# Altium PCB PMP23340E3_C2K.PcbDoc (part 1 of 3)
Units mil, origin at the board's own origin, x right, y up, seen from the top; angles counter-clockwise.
Board outline 2299.21 x 1157.48 mil, 14 copper layers (Top Layer, Layer 1, Layer 2, Layer 3, Layer 4, Layer 5, Layer 6, Layer 7, Layer 8, Layer 9, Layer 10, Layer 11, Layer 12, Bottom Layer), stack 130 mil thick; 241 components, 70 nets, 1009 pads, 327 vias.
Unrouted connection lines stored in the file: 7.
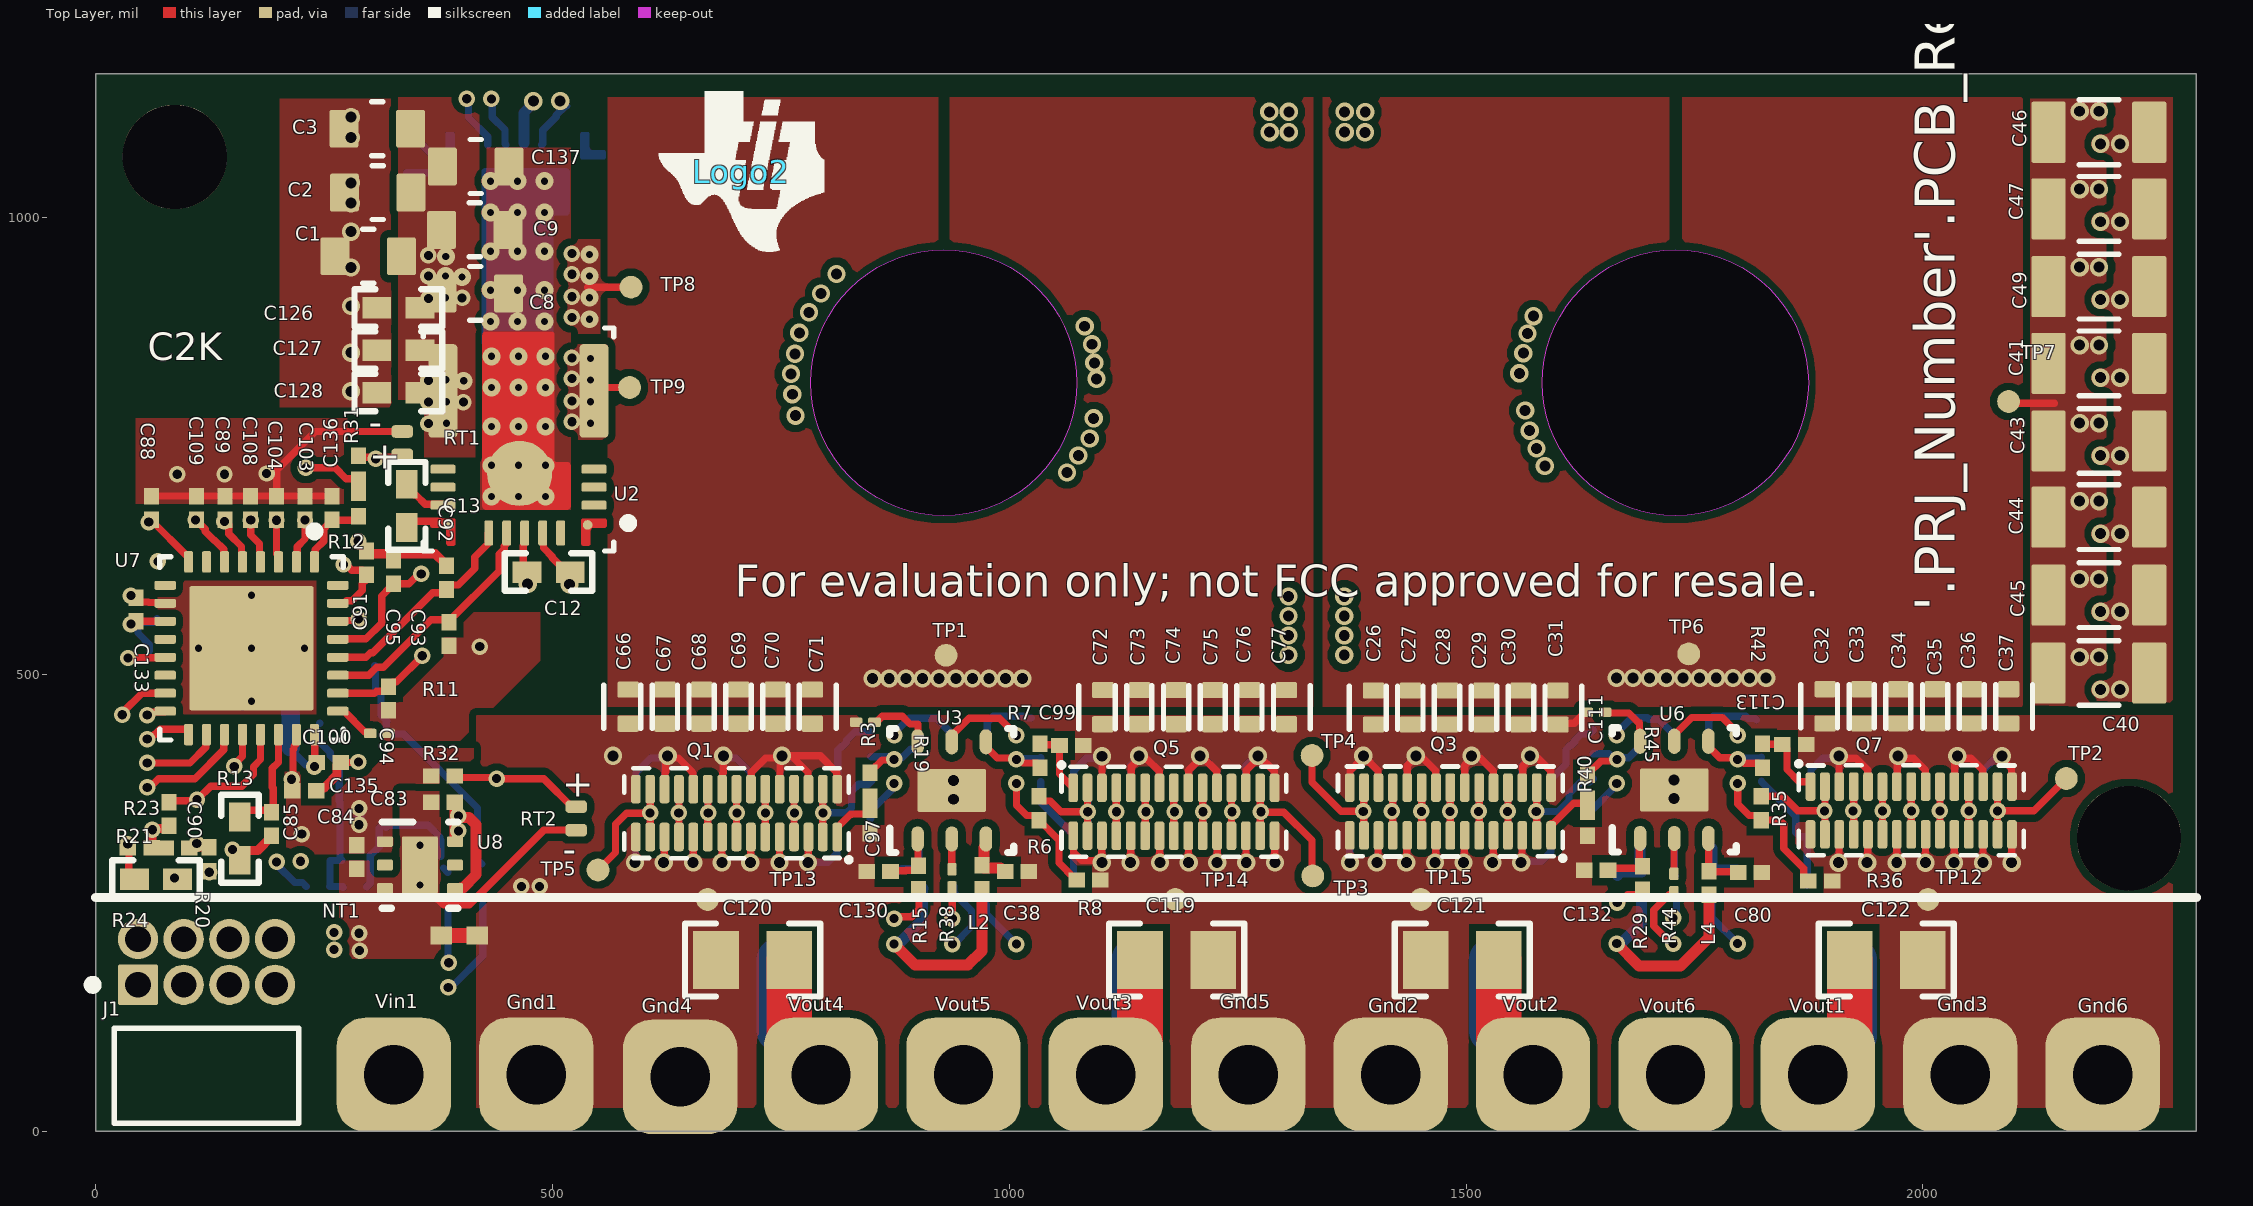
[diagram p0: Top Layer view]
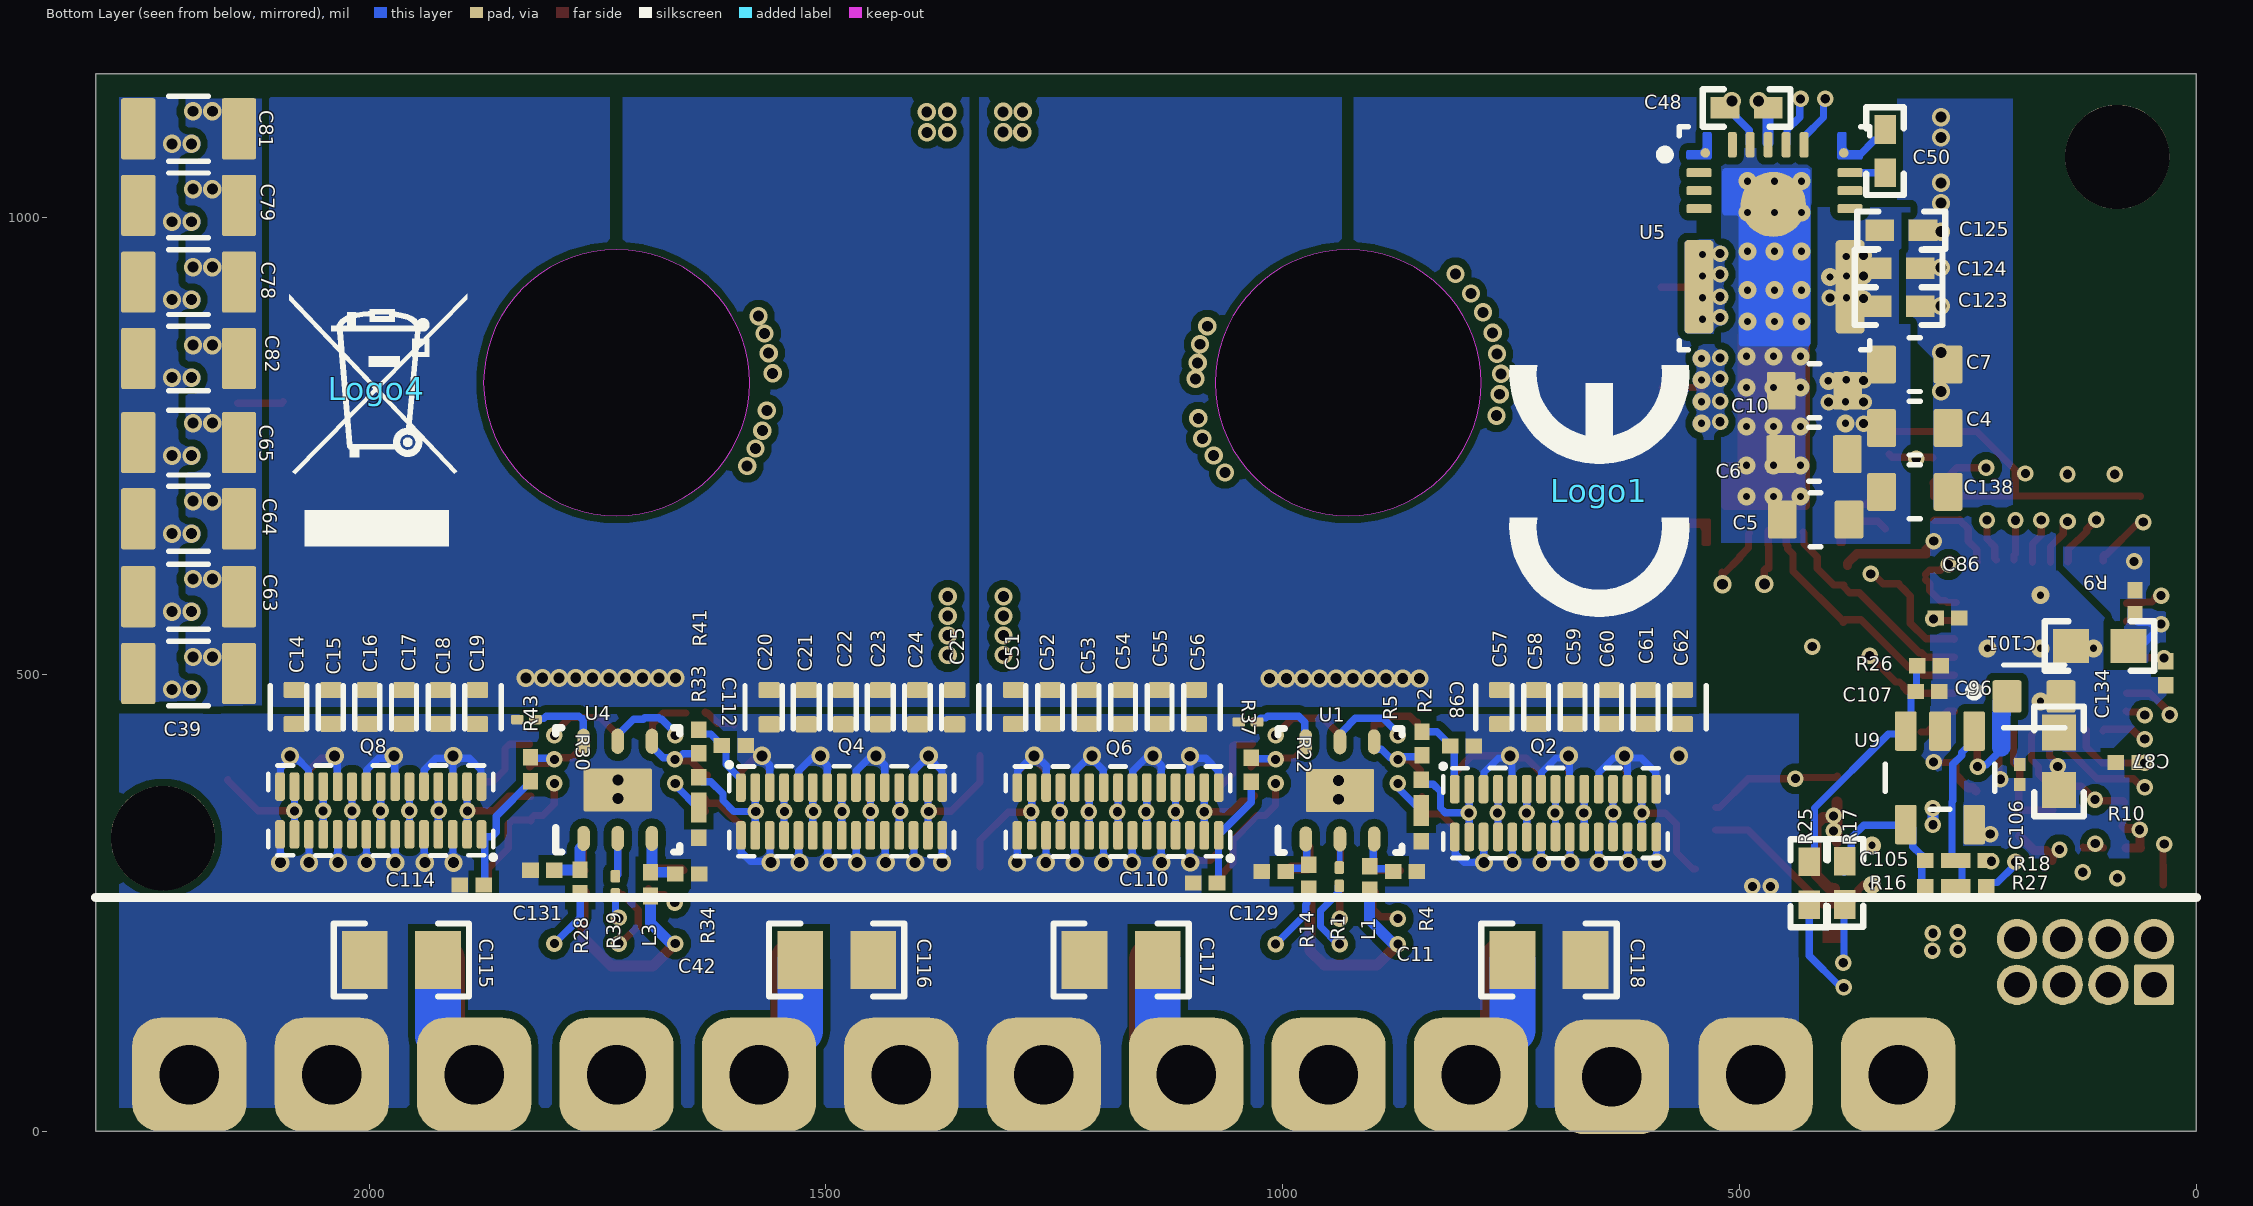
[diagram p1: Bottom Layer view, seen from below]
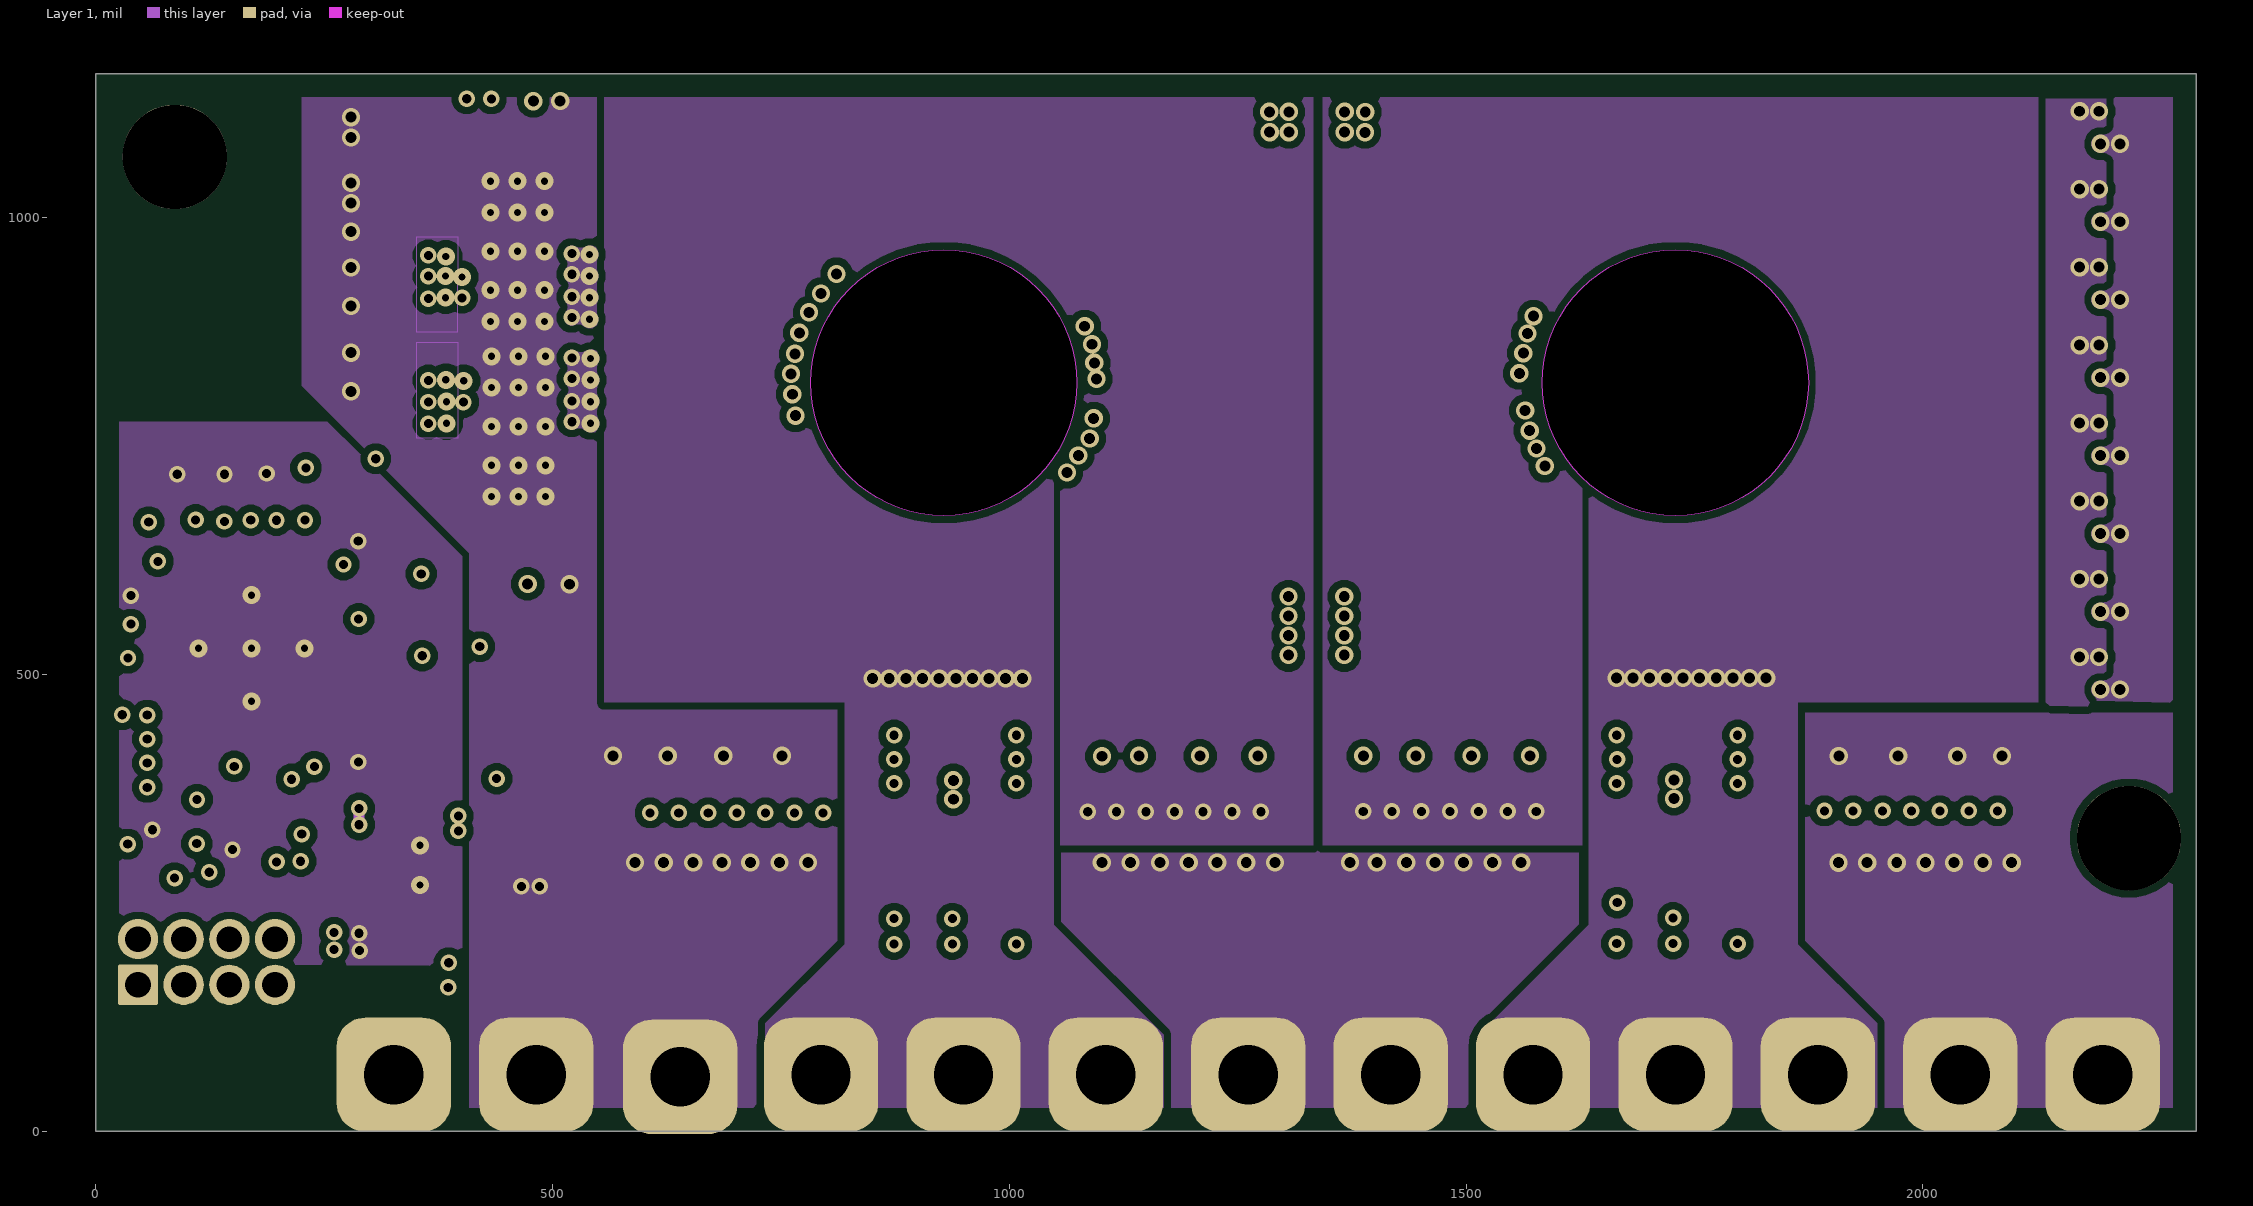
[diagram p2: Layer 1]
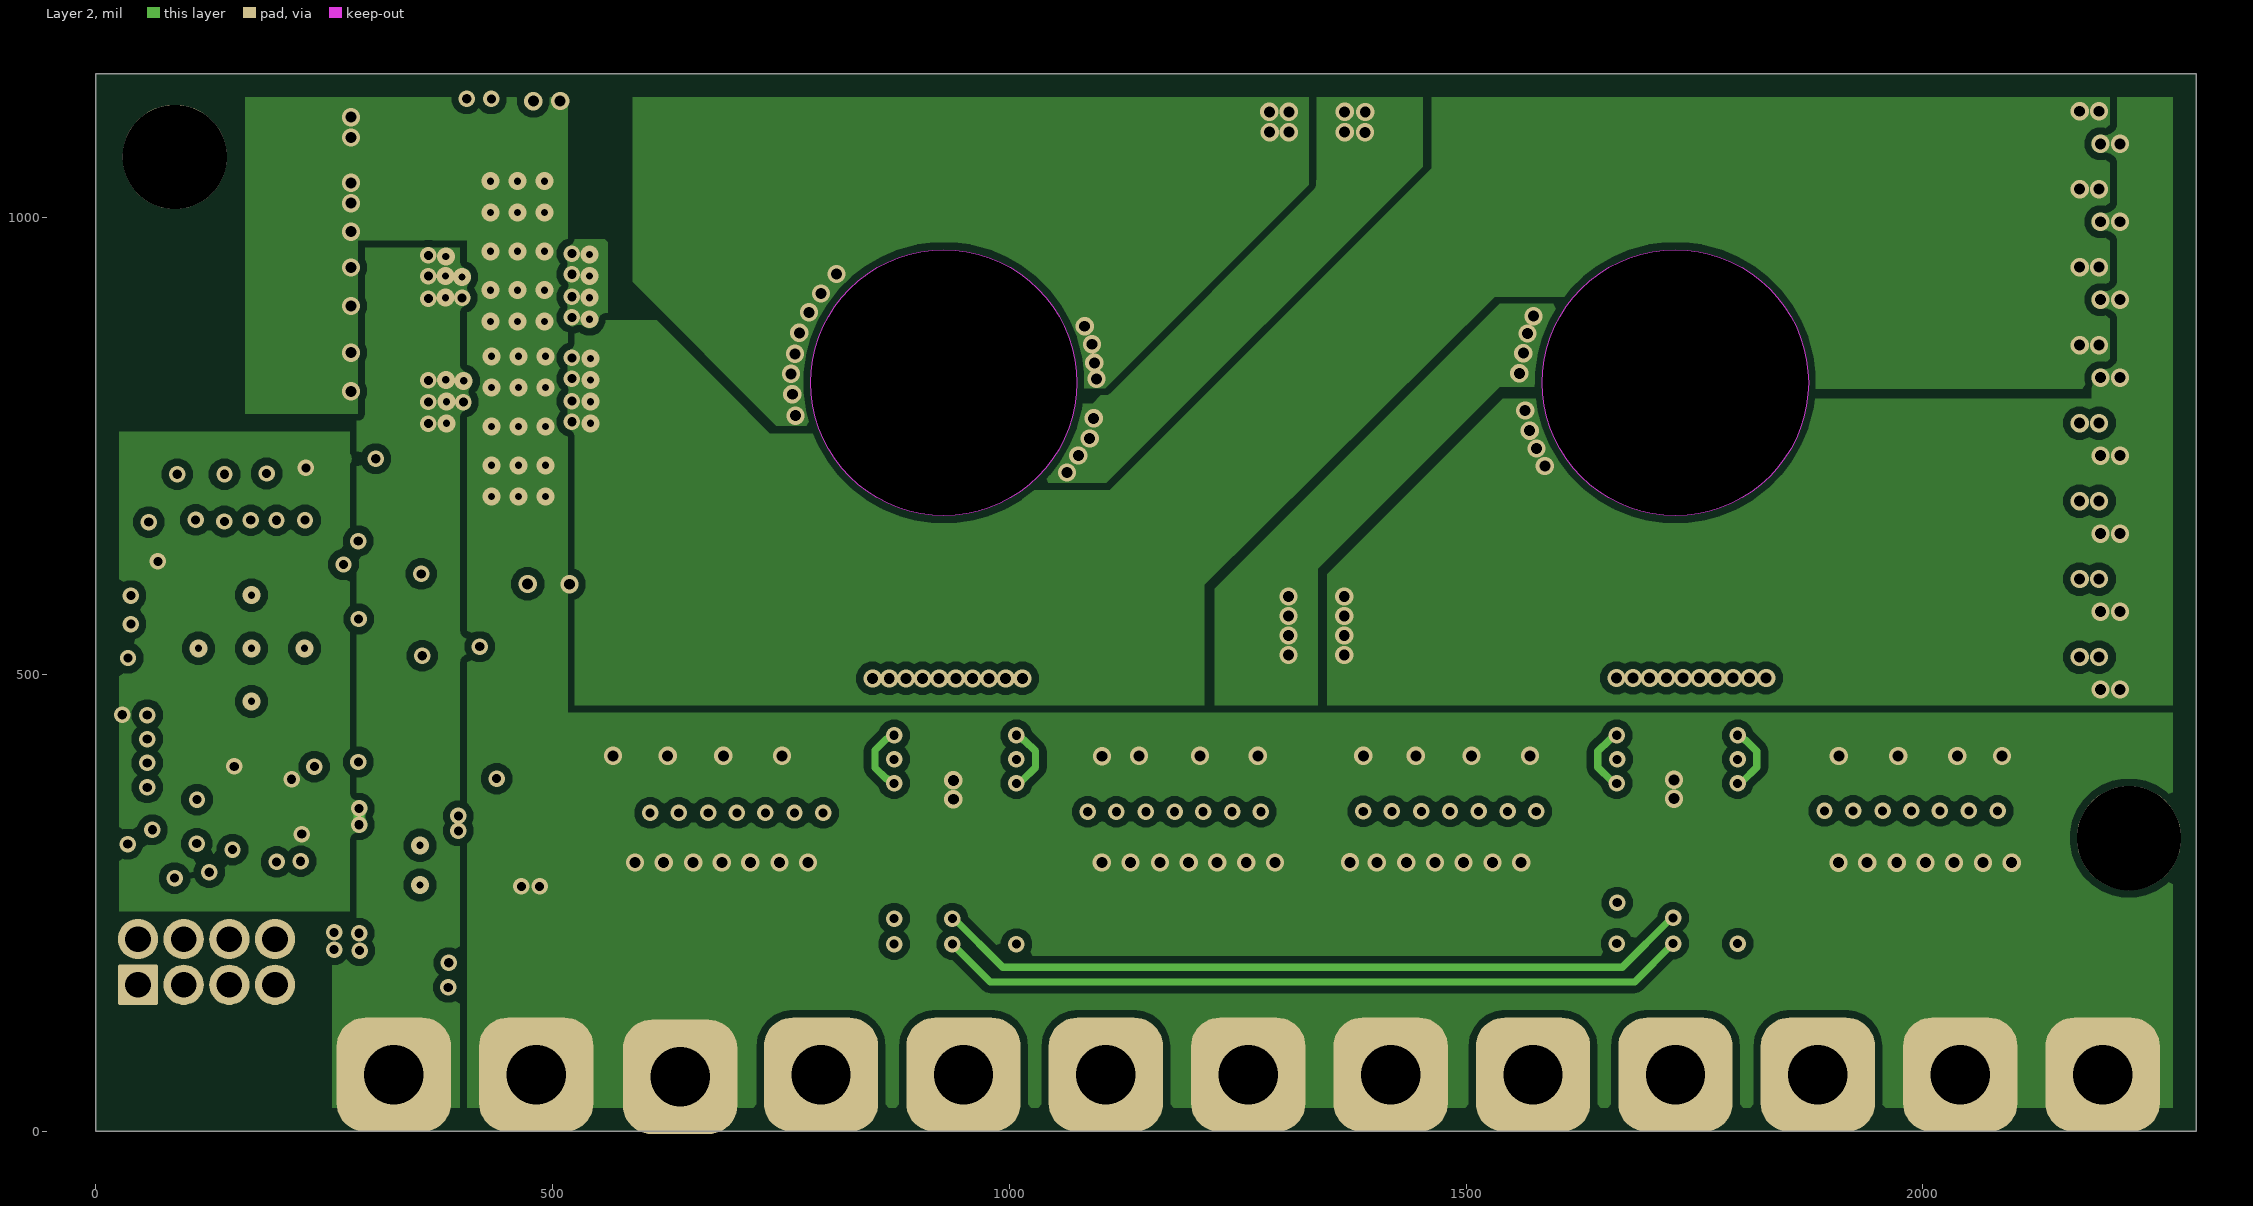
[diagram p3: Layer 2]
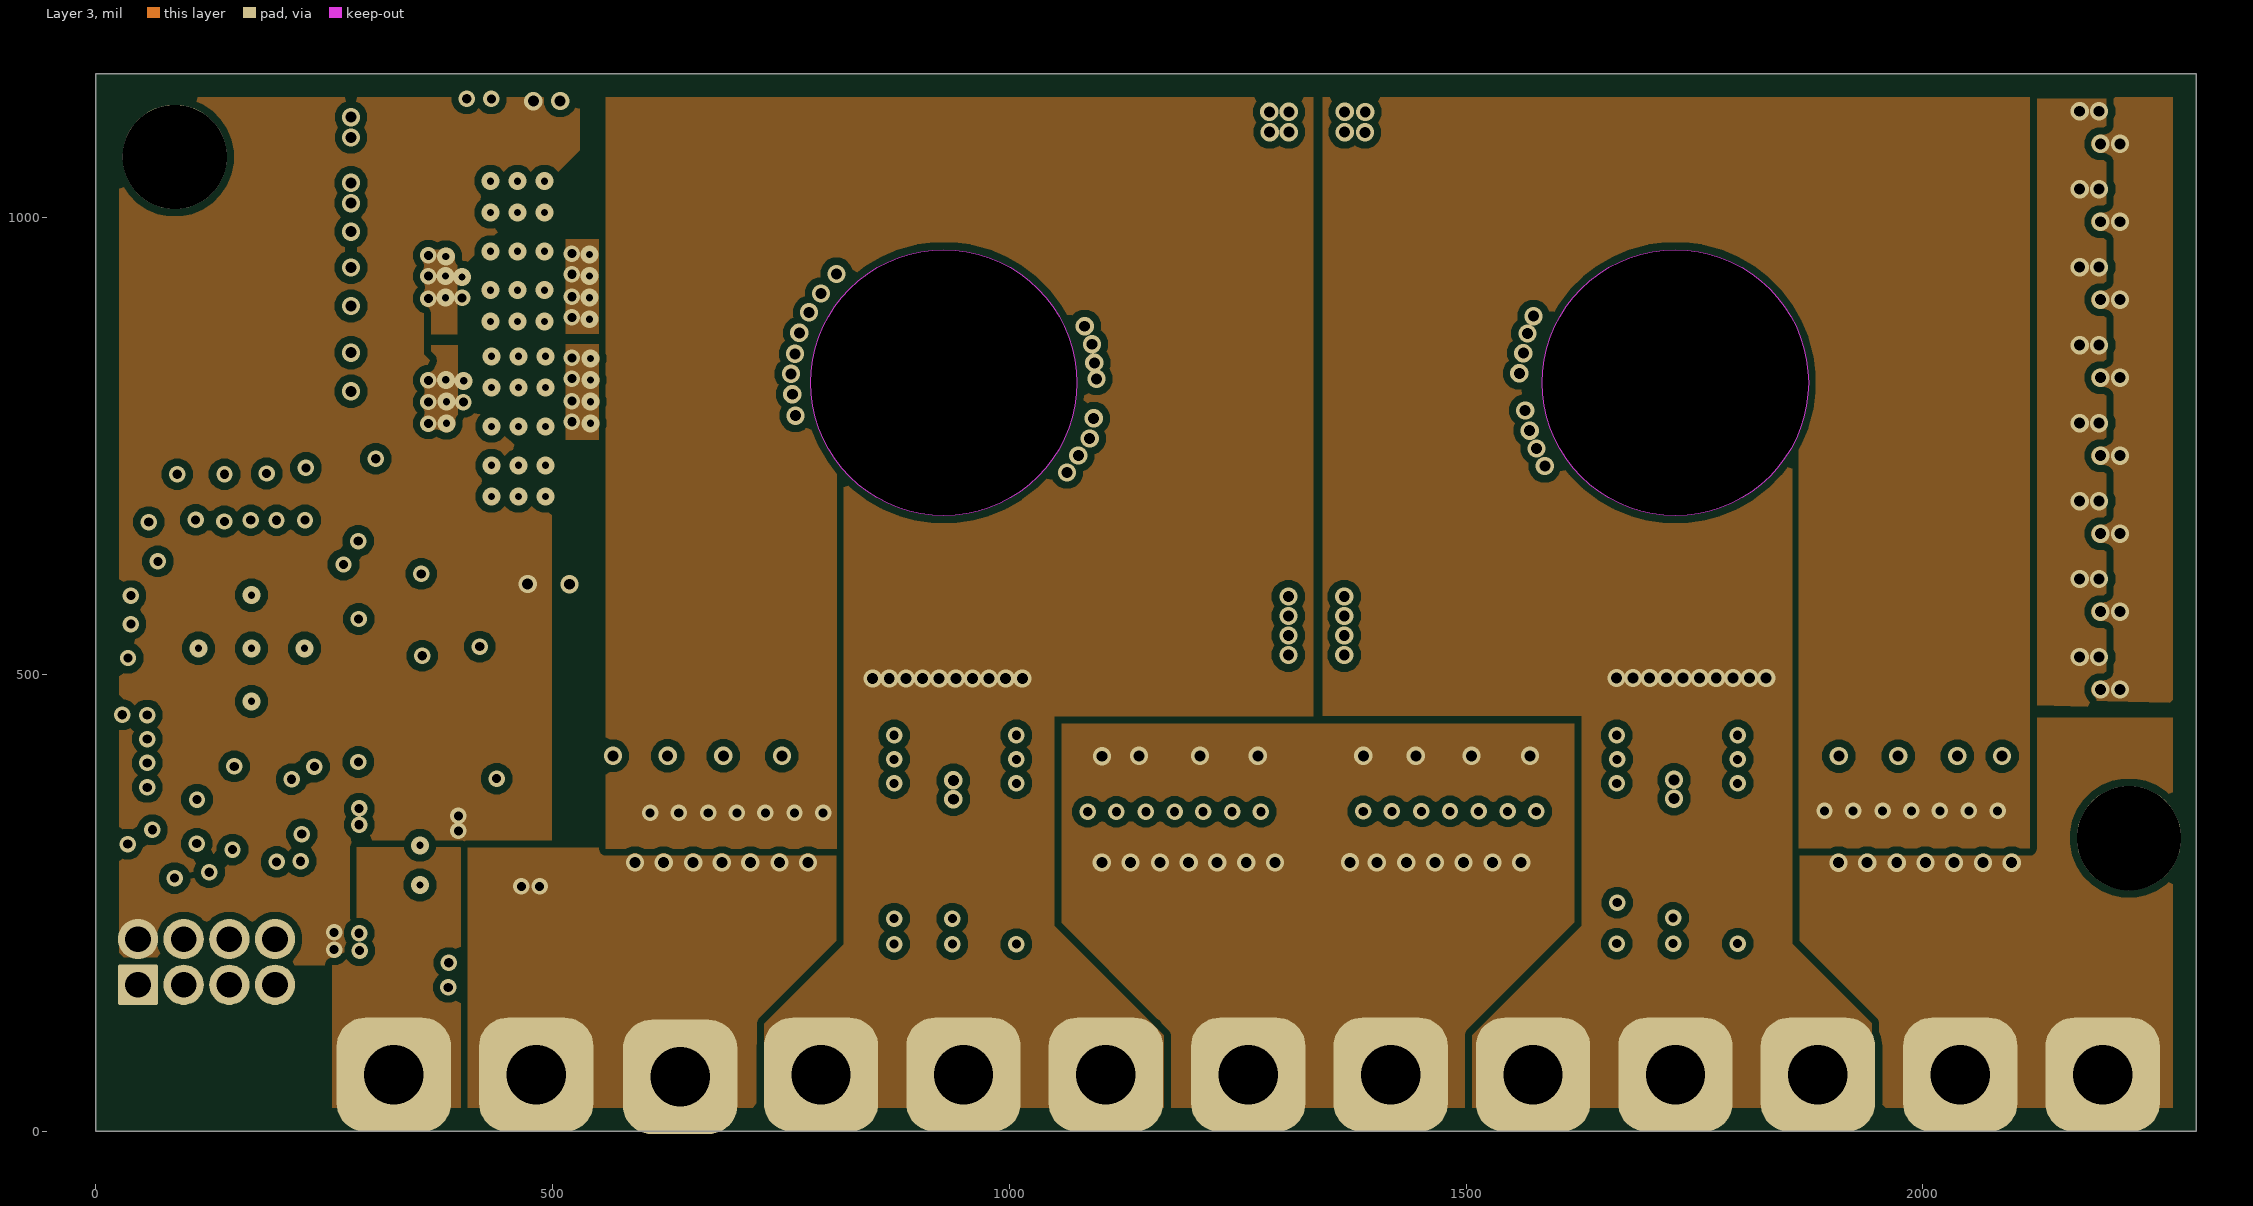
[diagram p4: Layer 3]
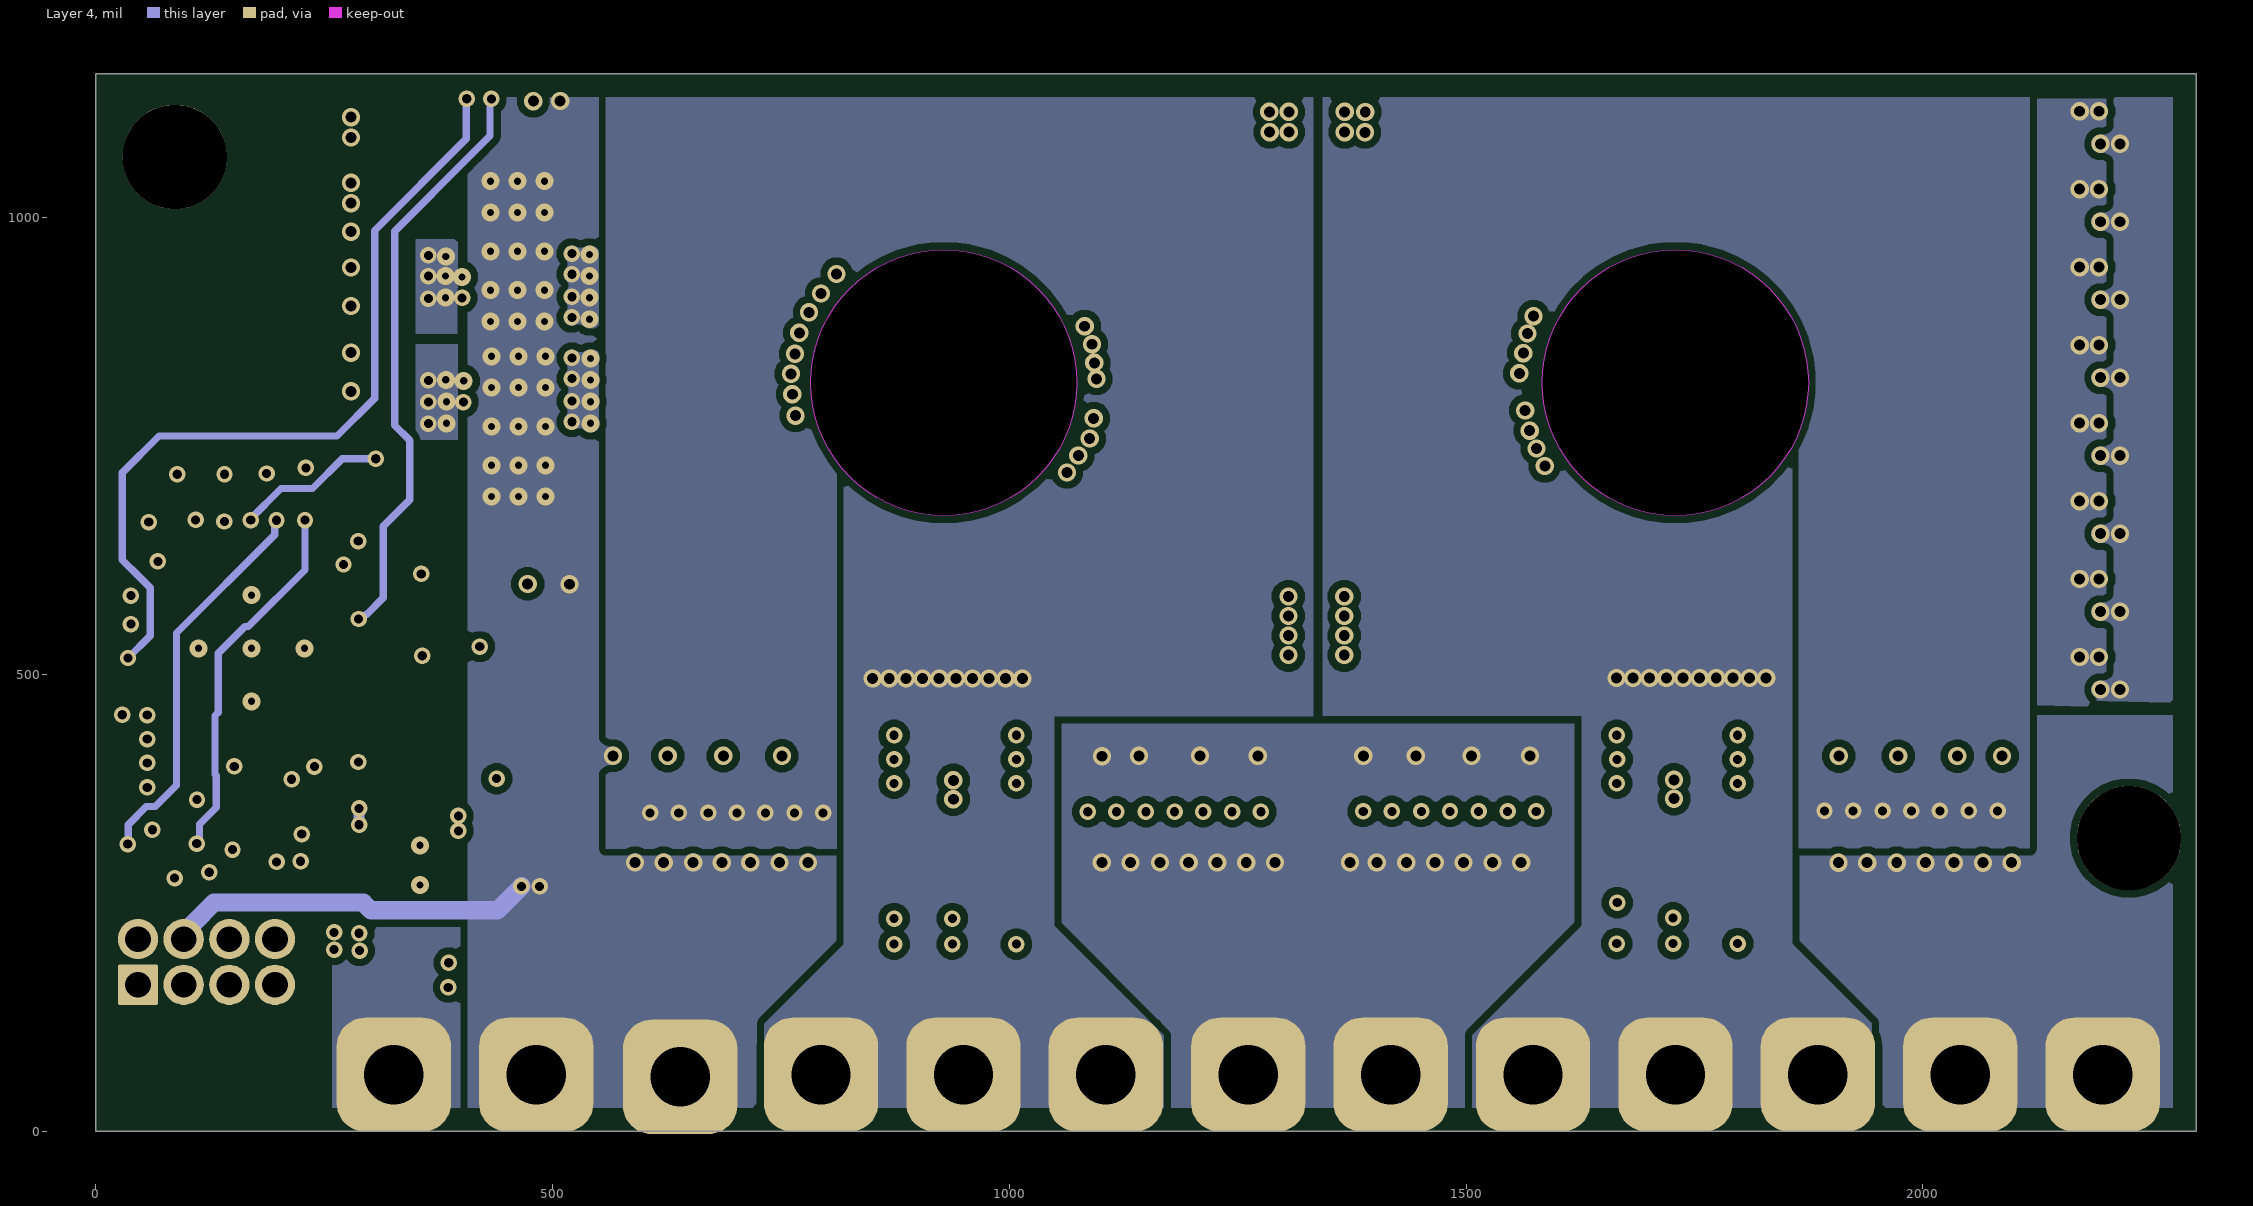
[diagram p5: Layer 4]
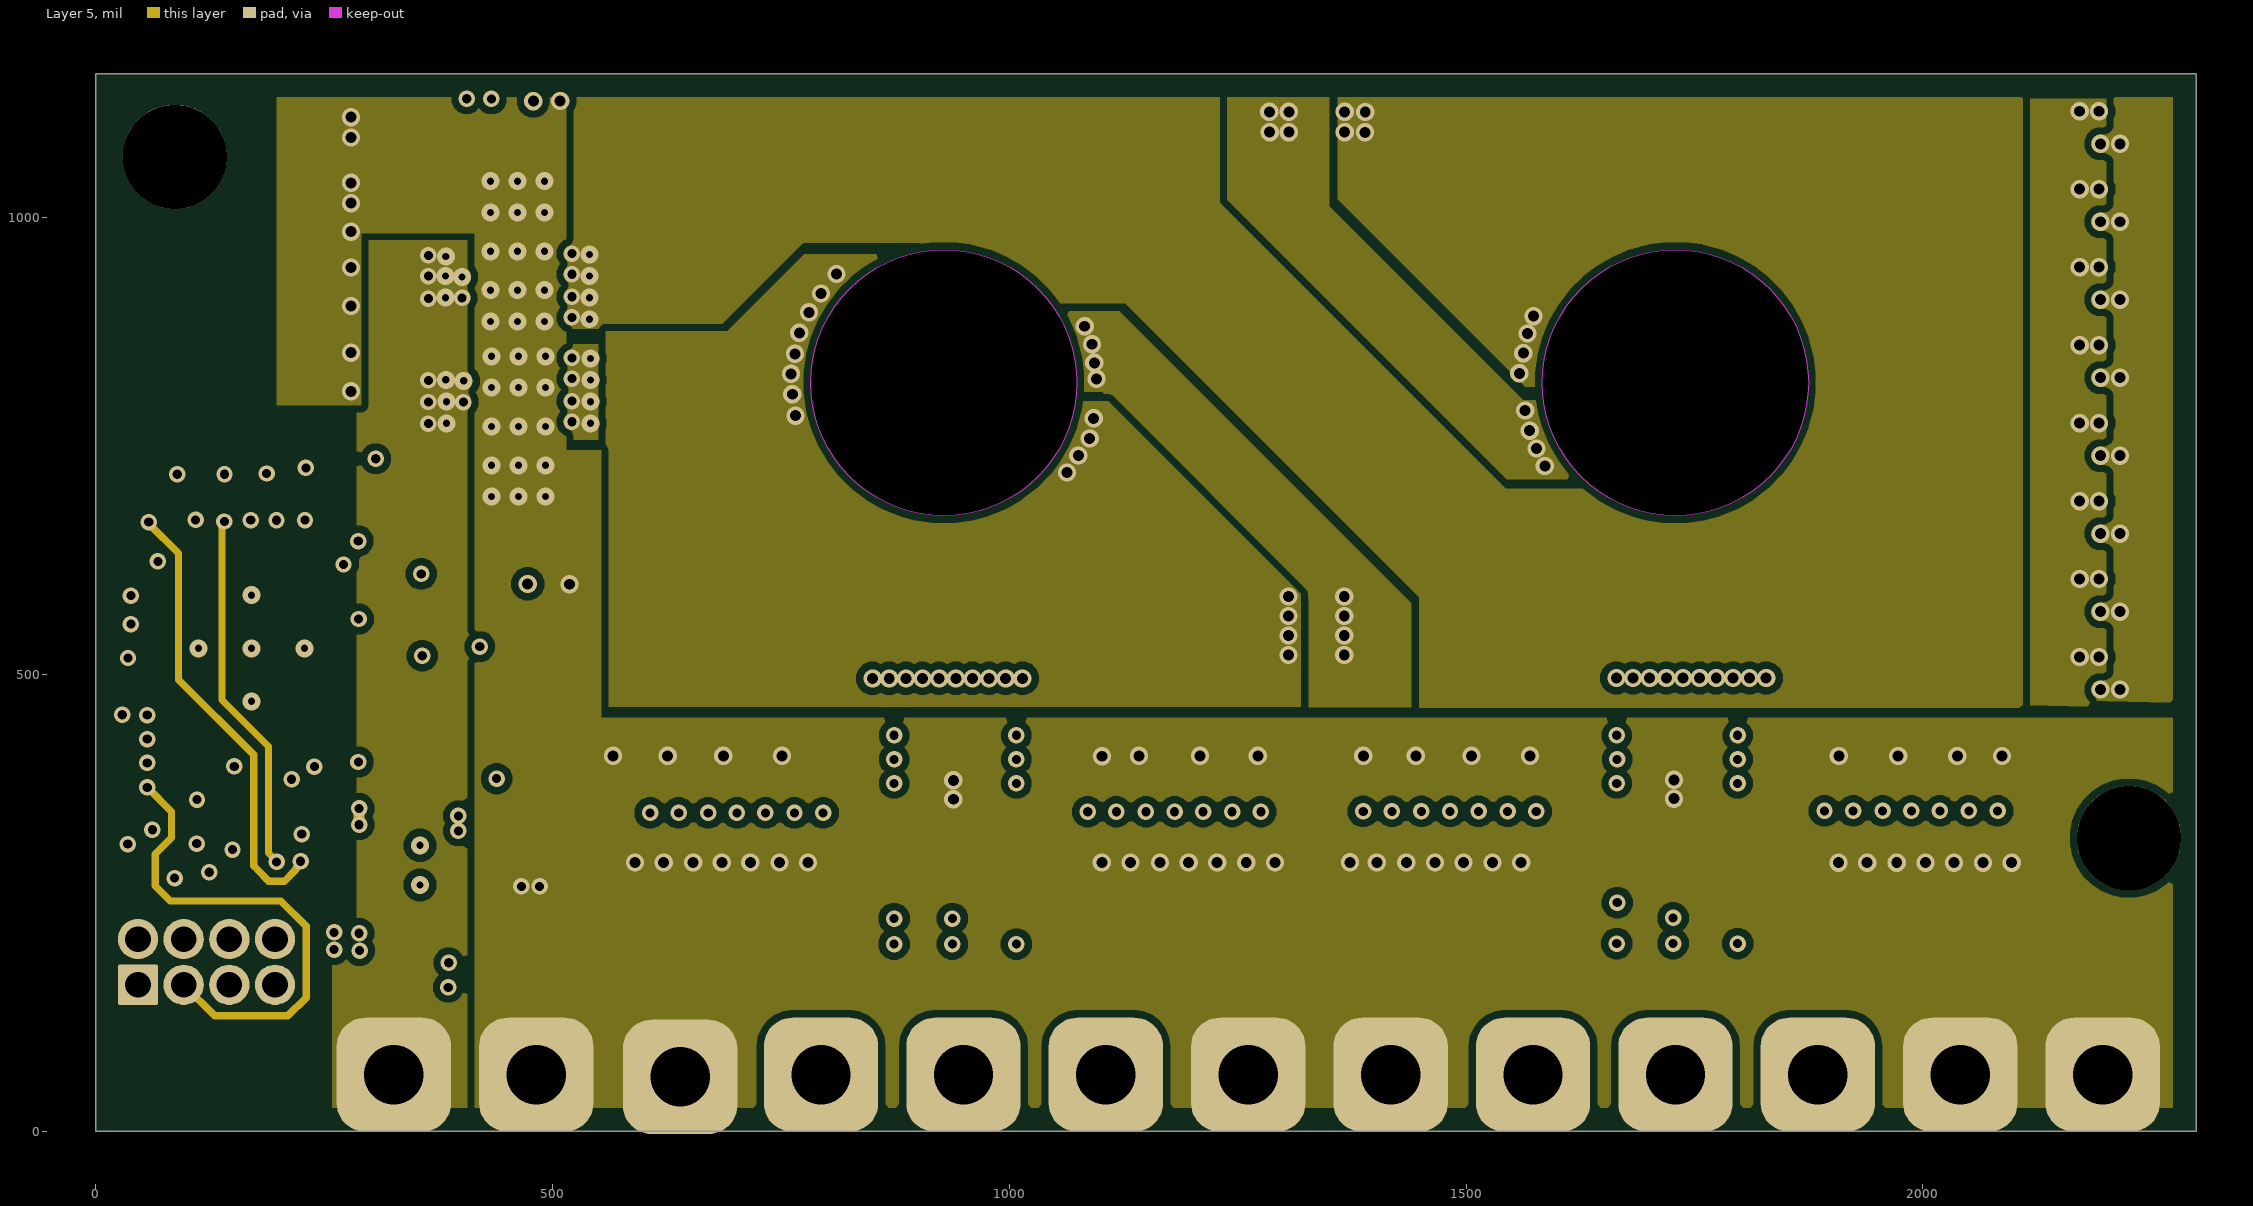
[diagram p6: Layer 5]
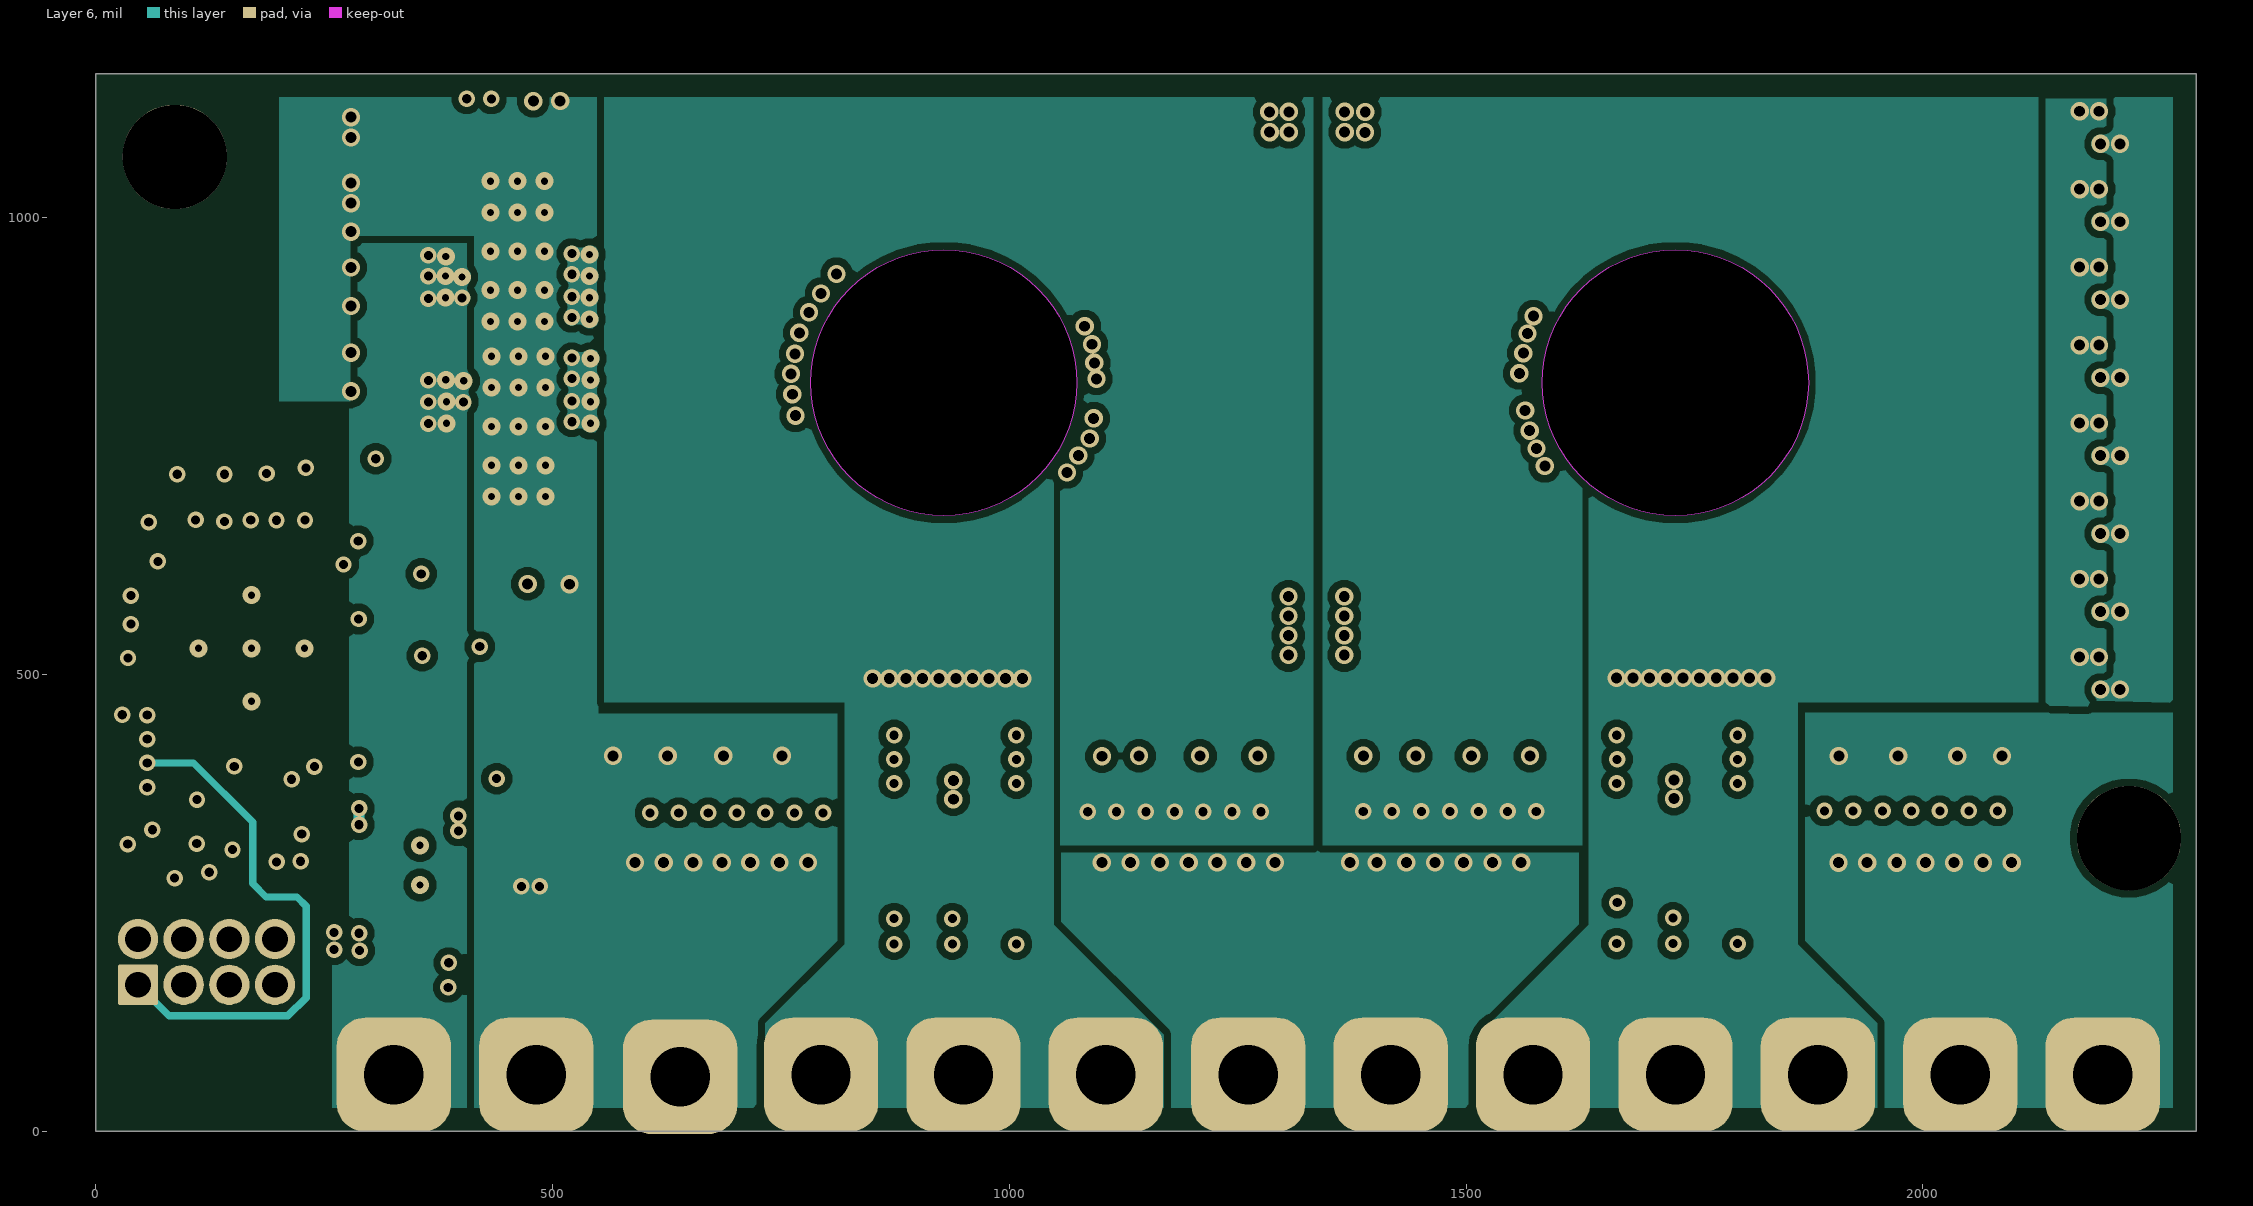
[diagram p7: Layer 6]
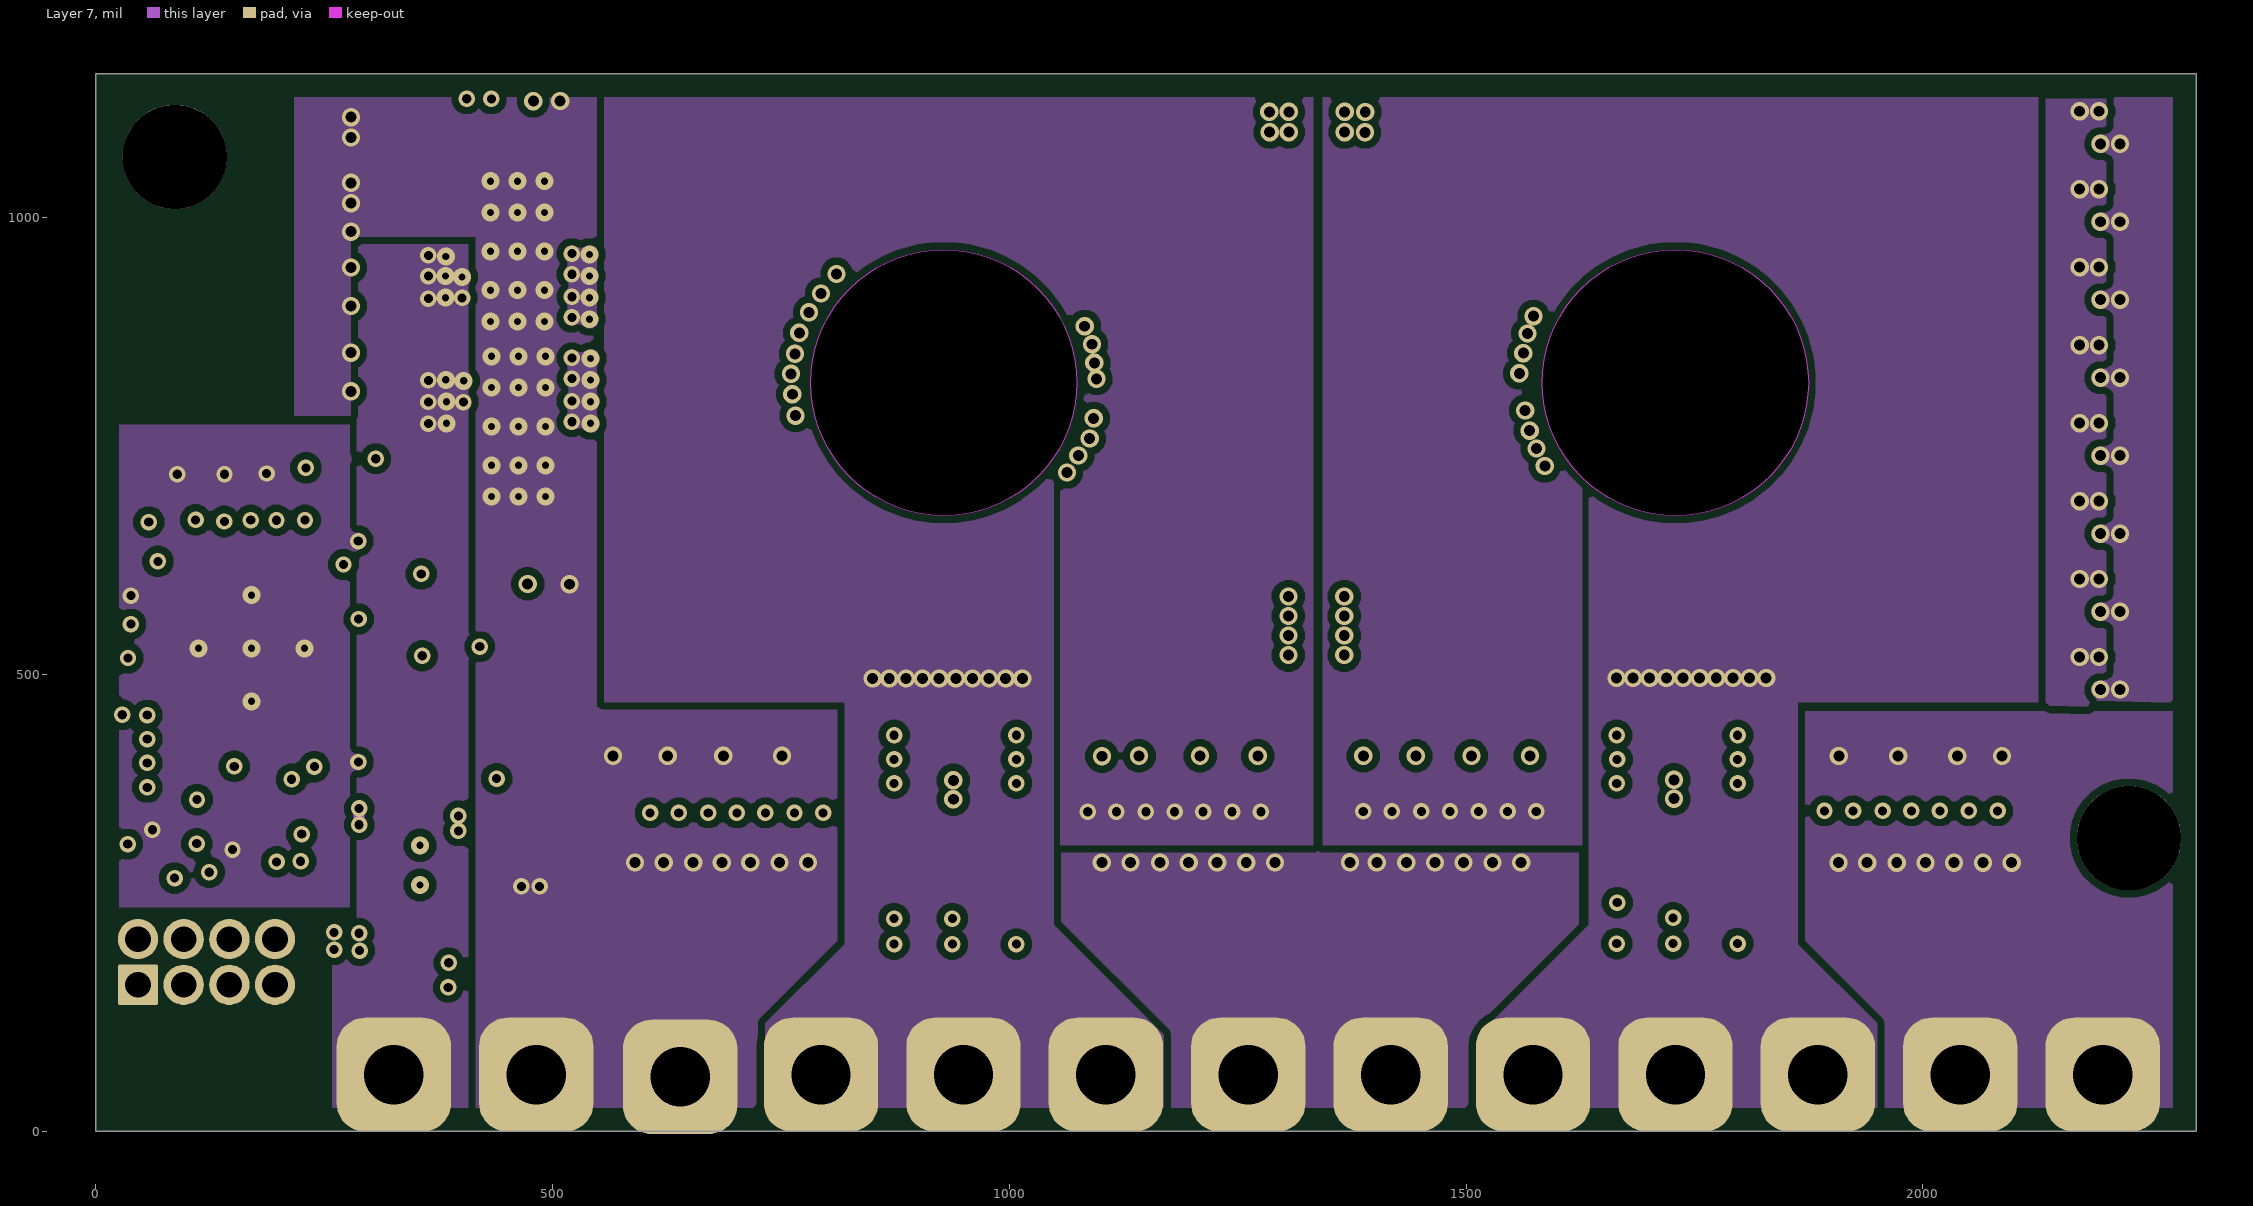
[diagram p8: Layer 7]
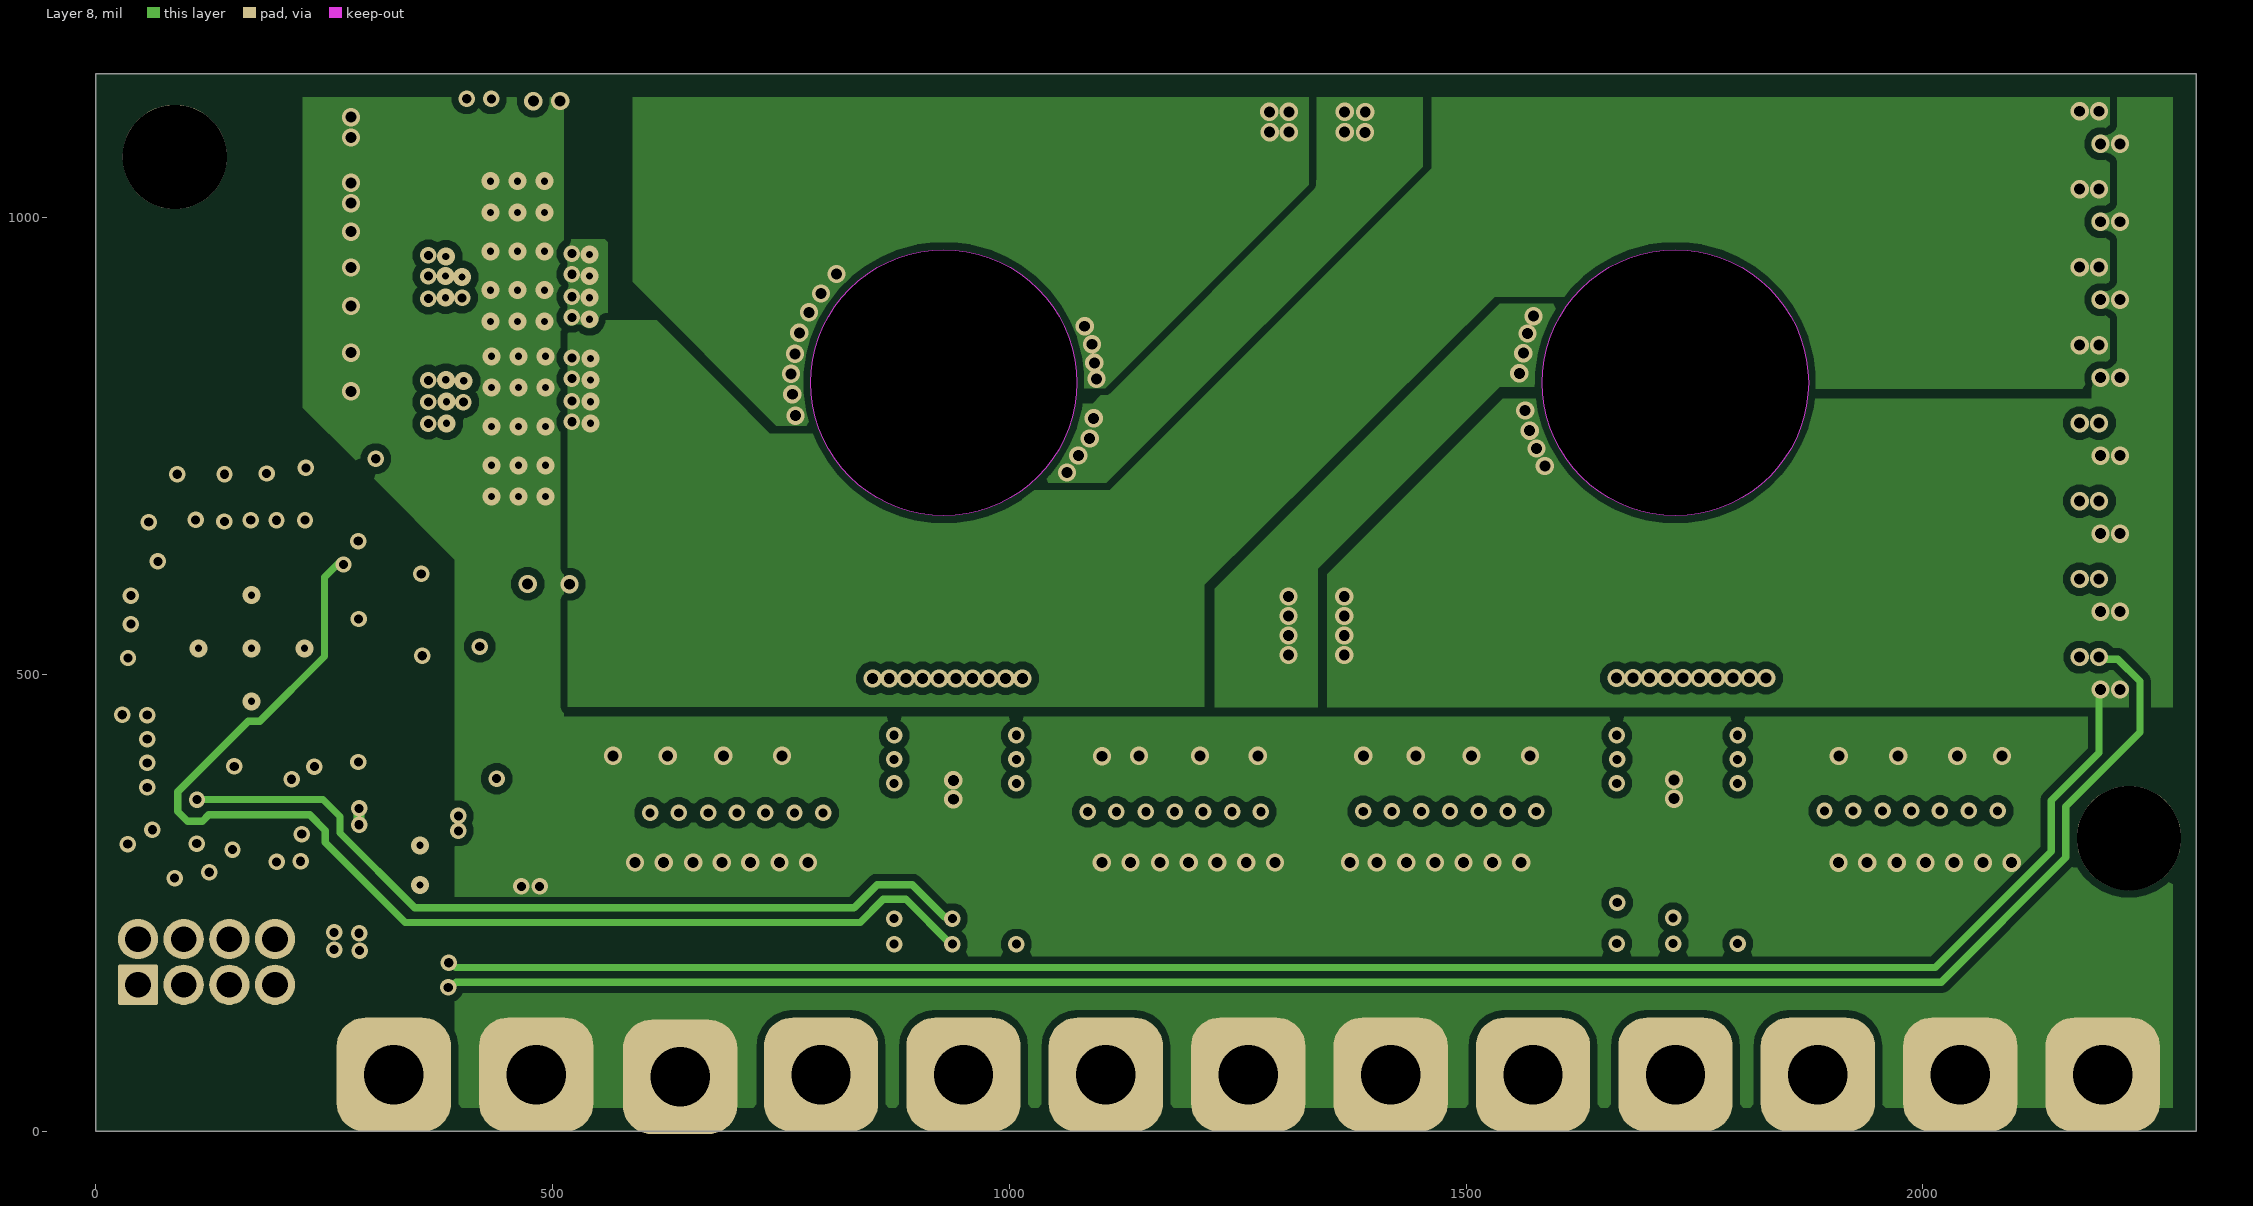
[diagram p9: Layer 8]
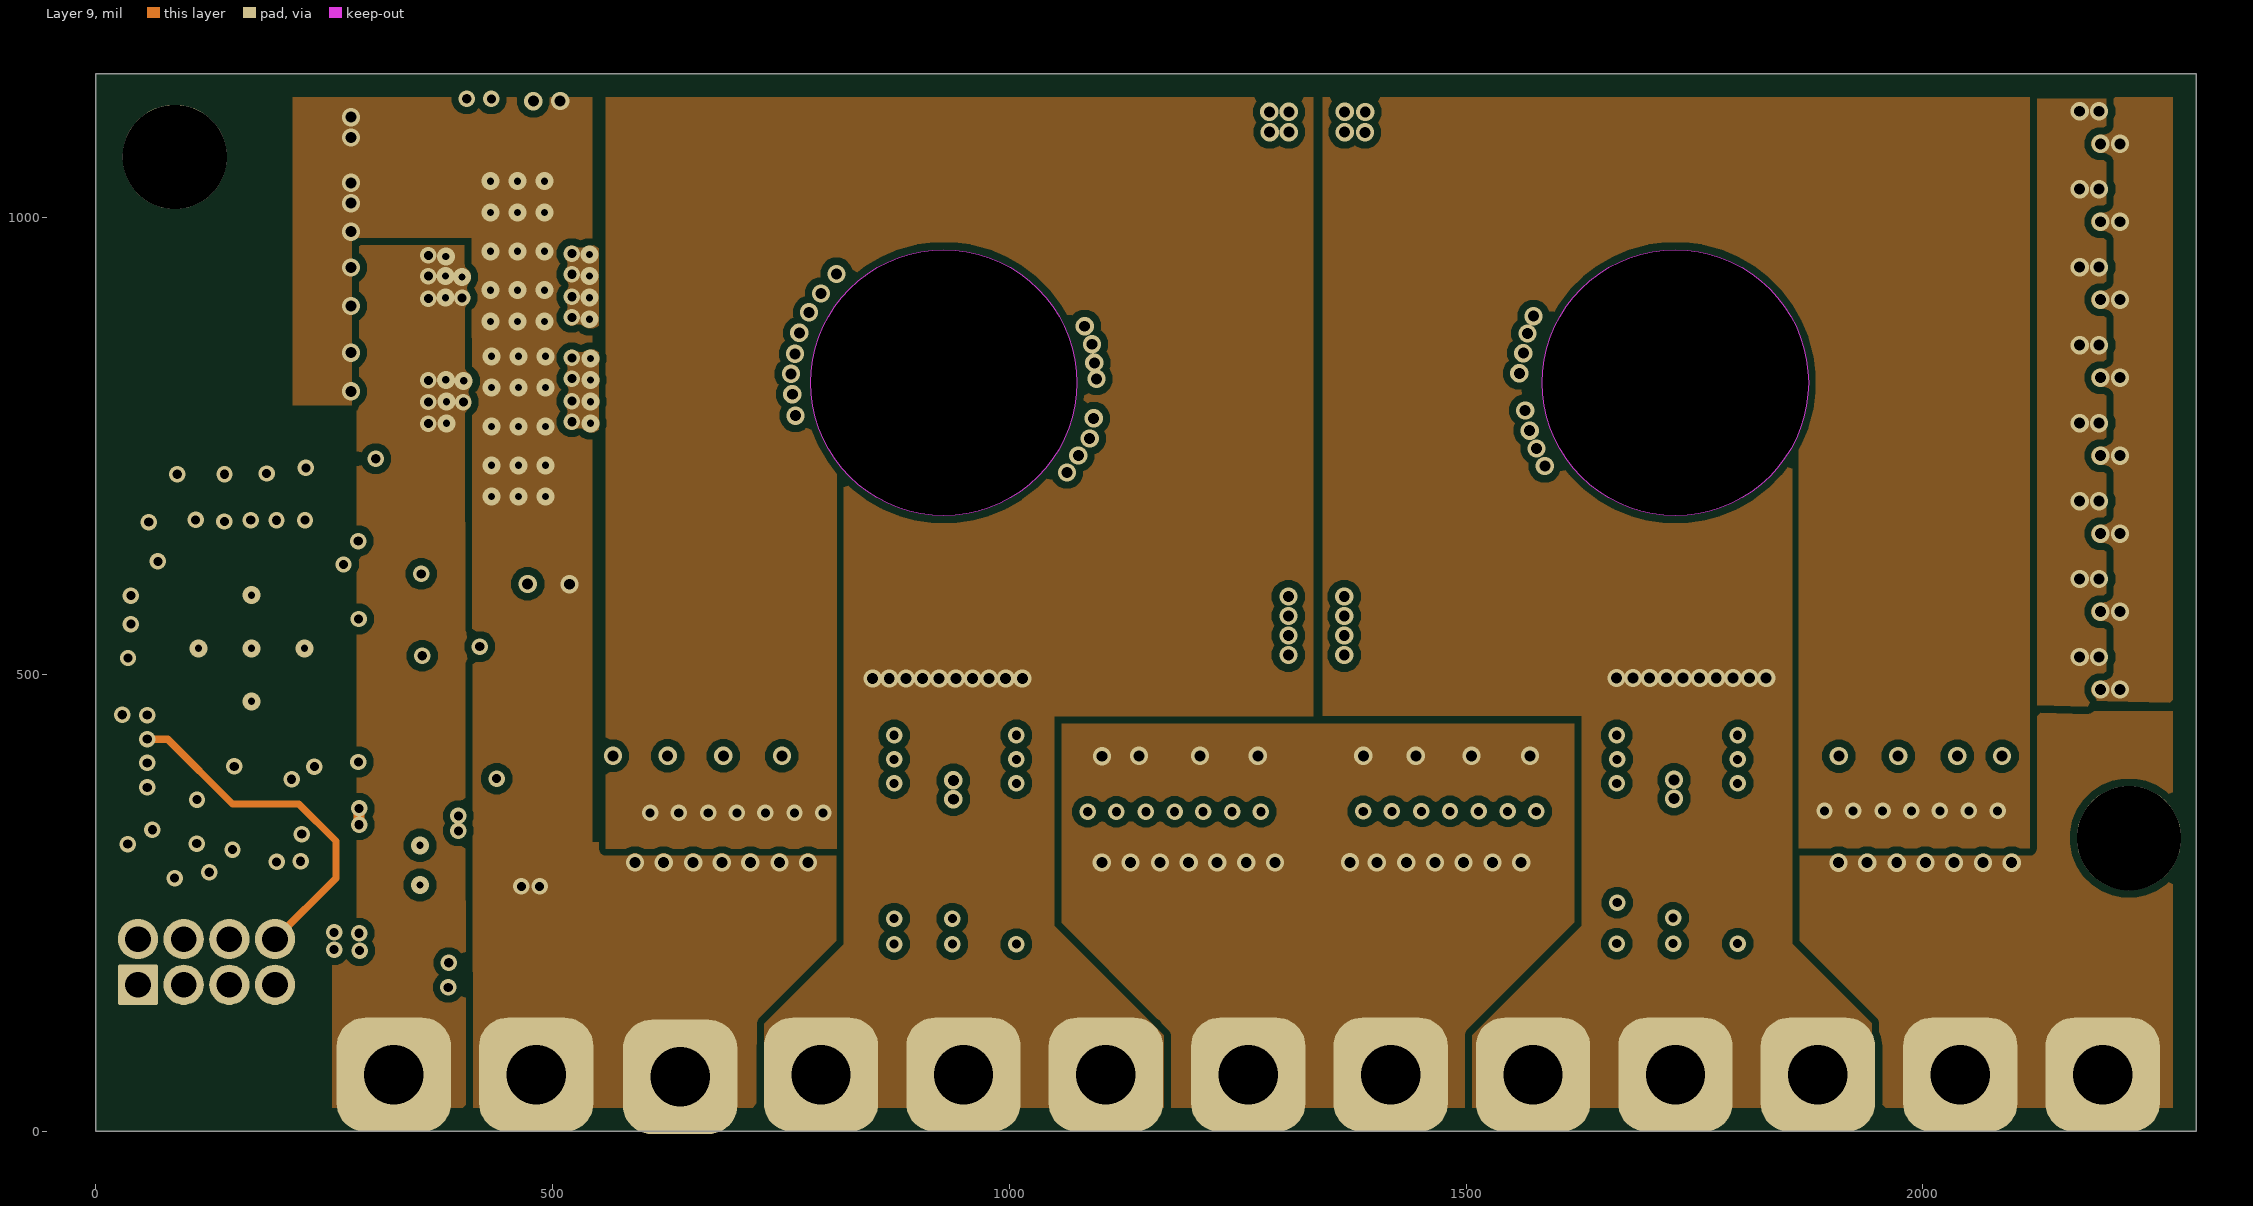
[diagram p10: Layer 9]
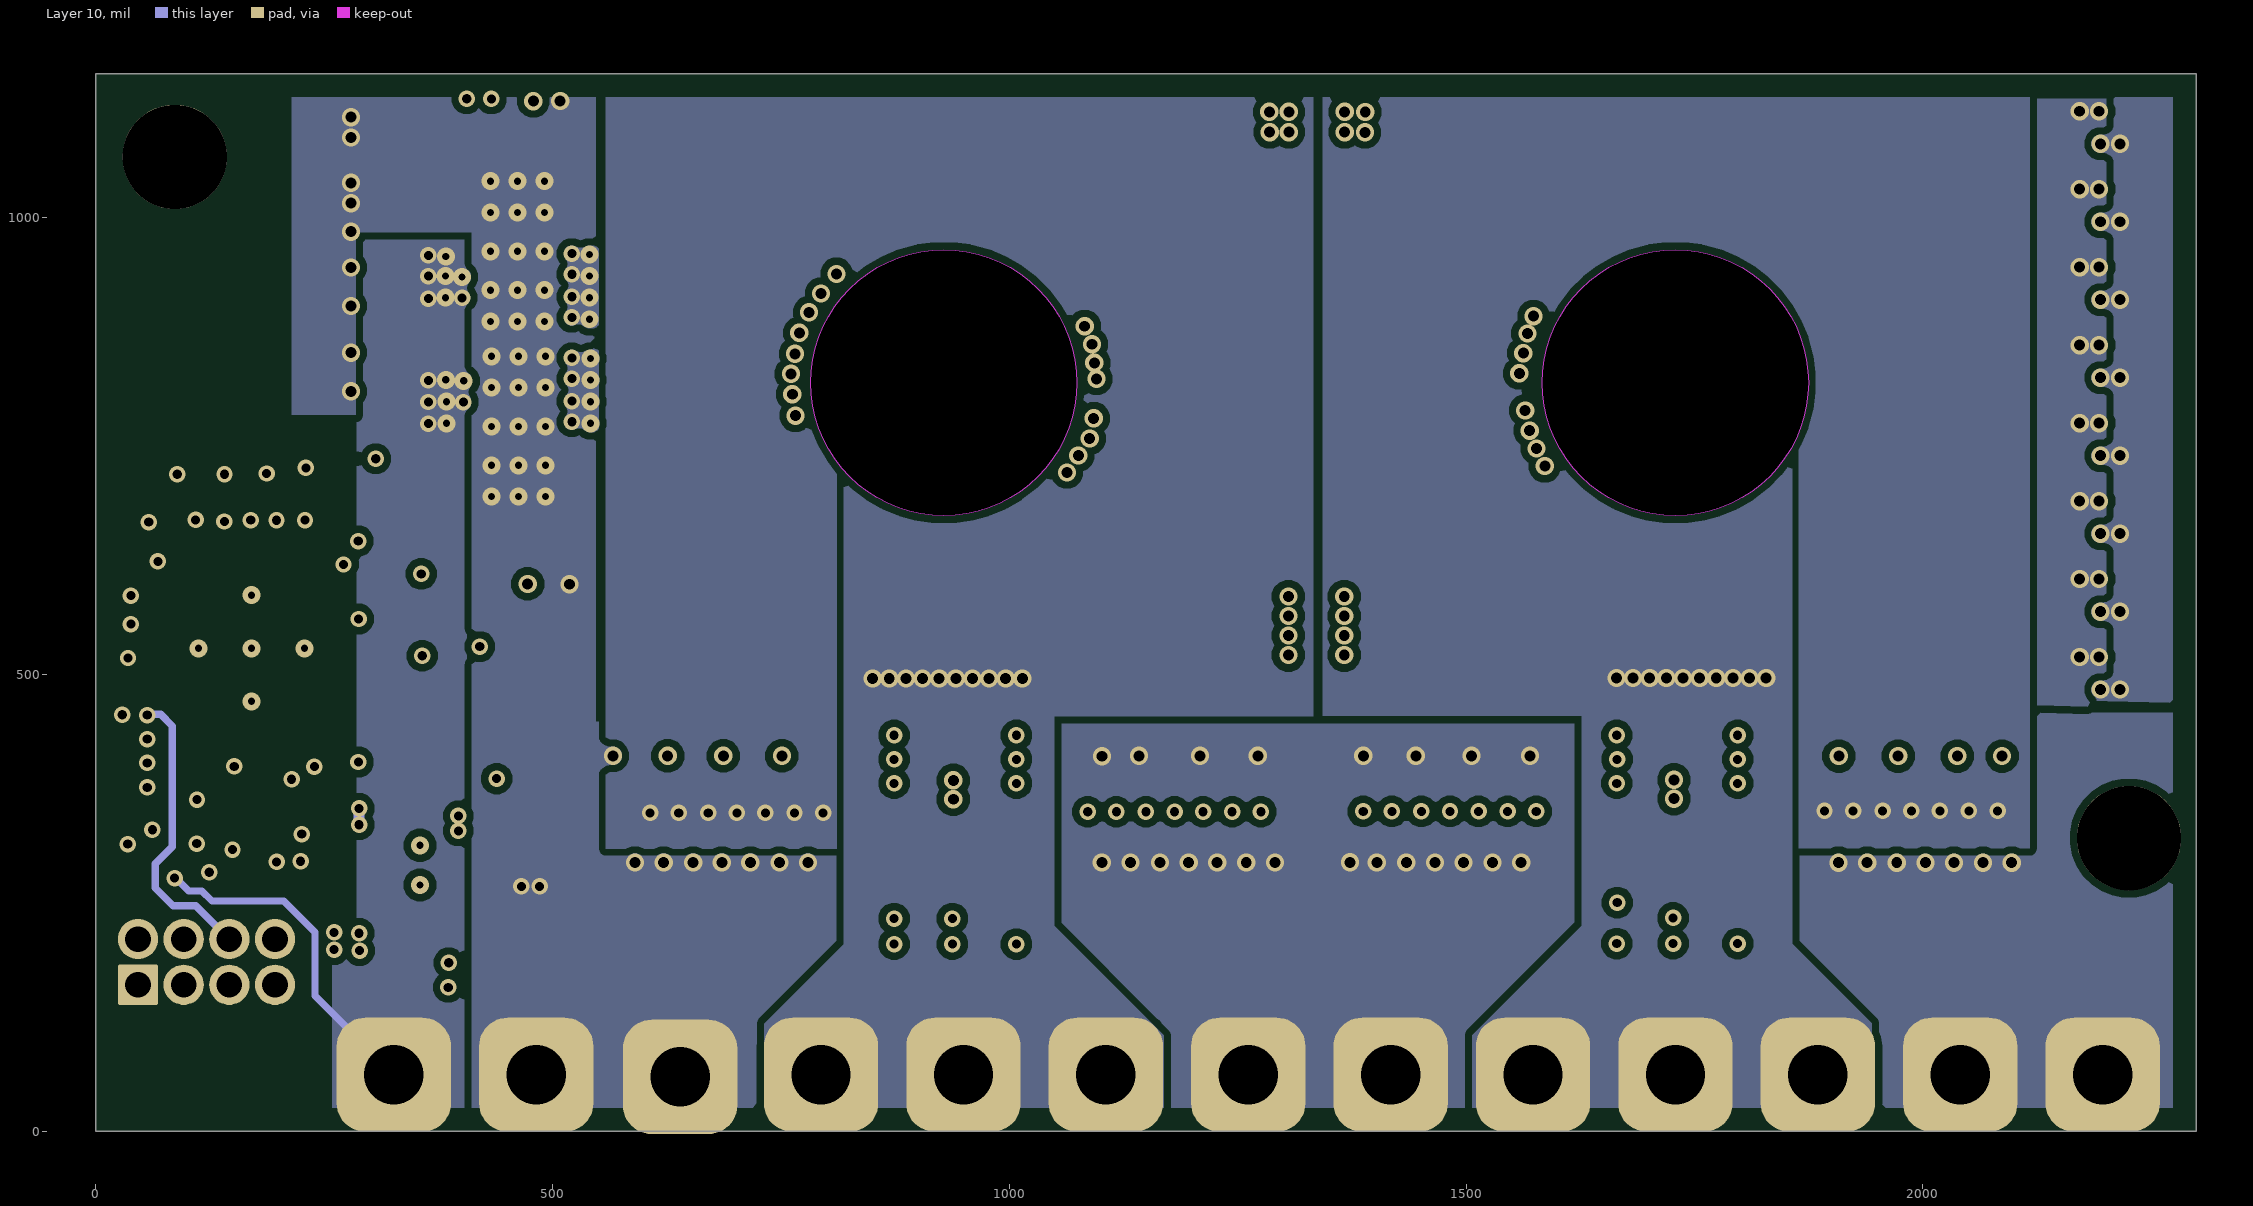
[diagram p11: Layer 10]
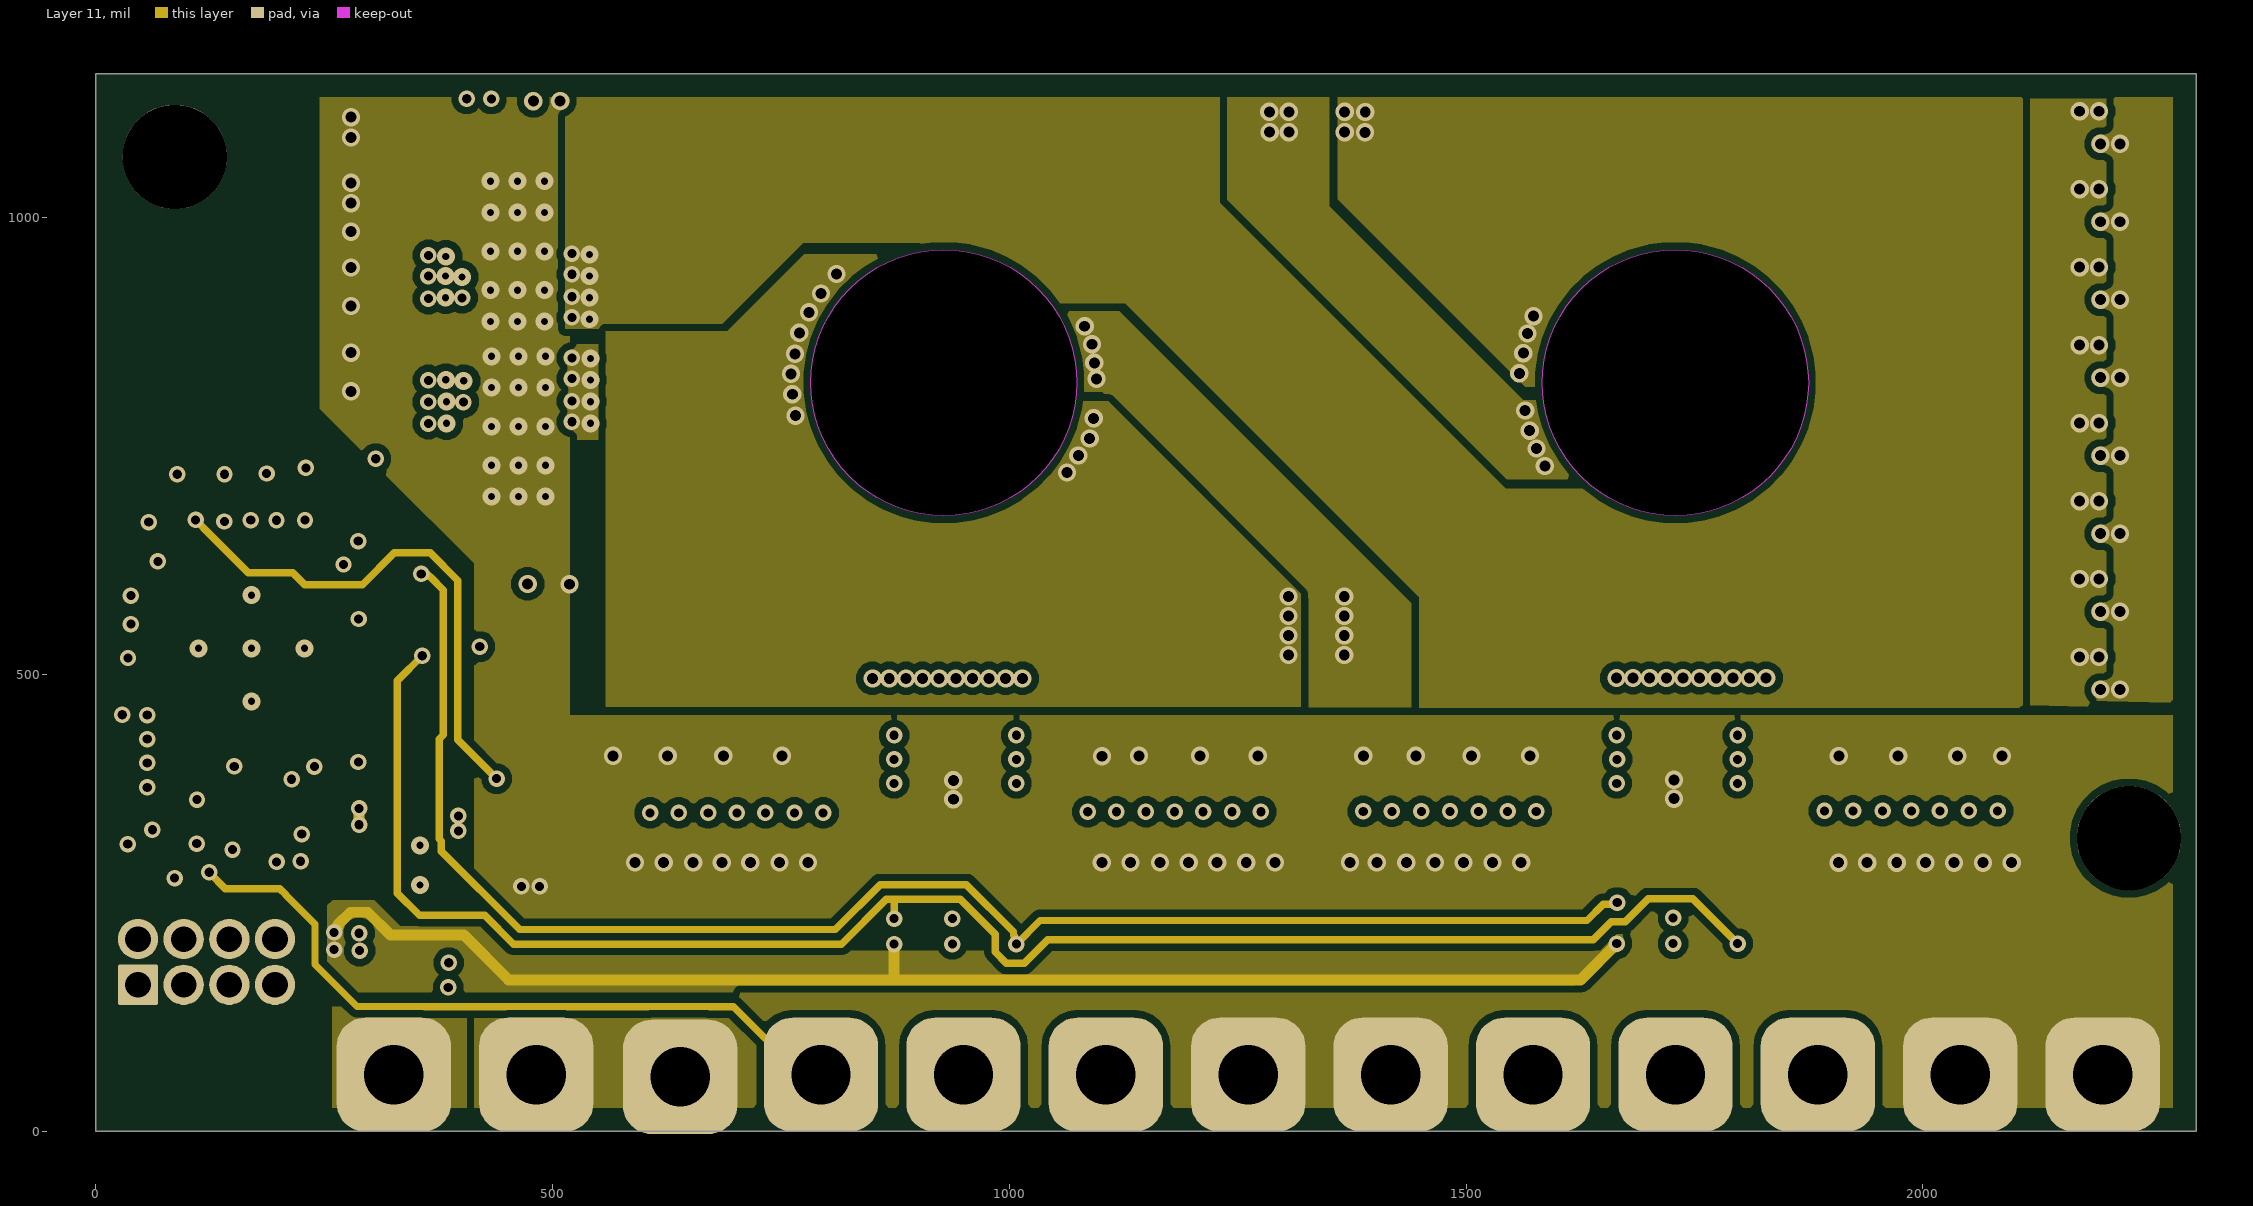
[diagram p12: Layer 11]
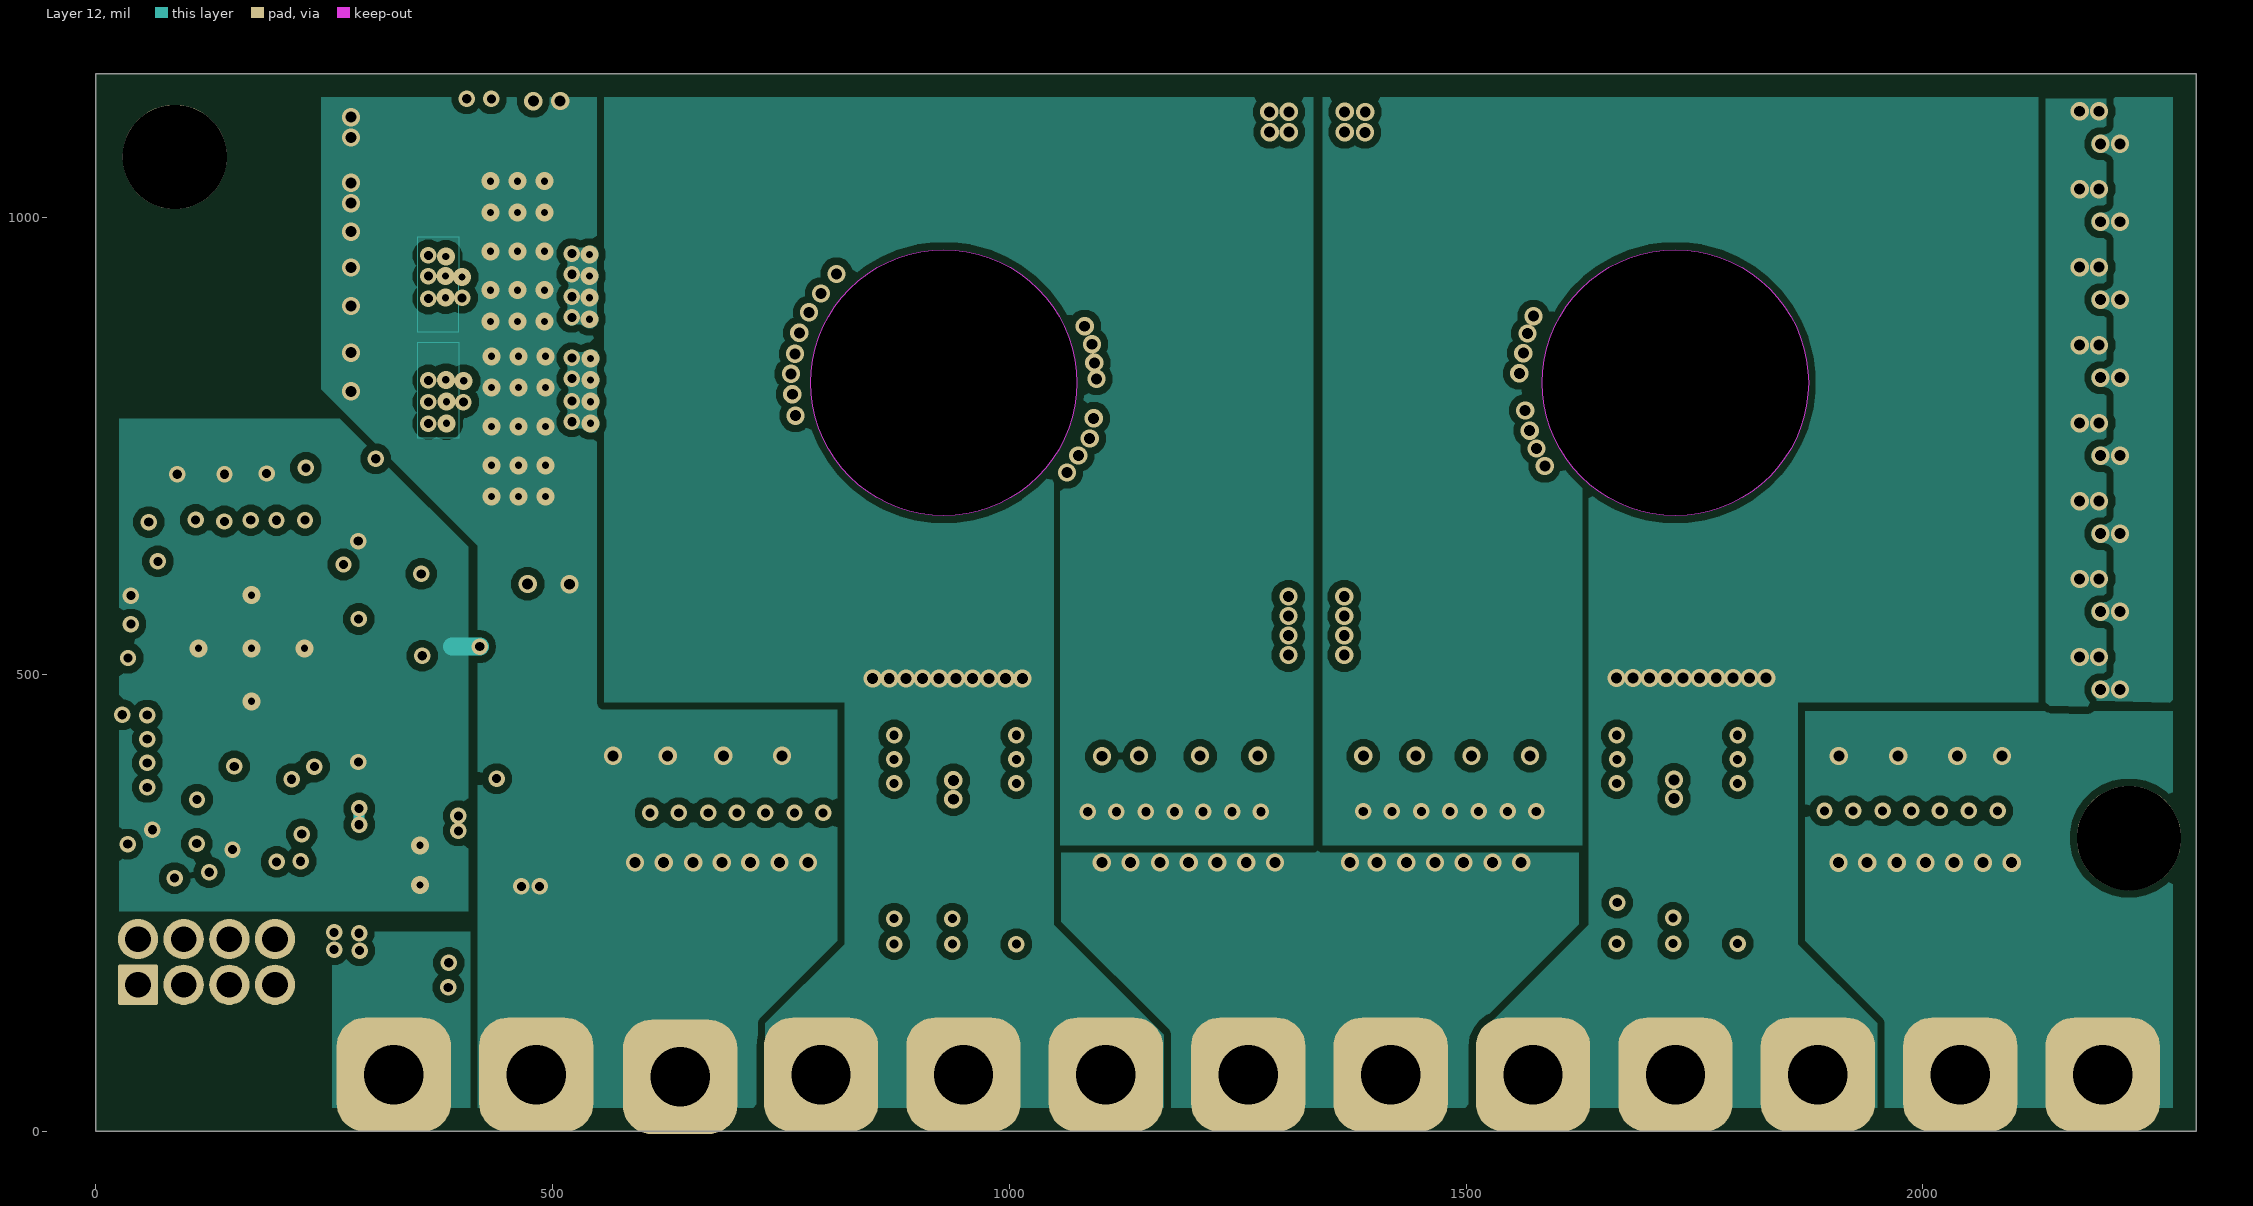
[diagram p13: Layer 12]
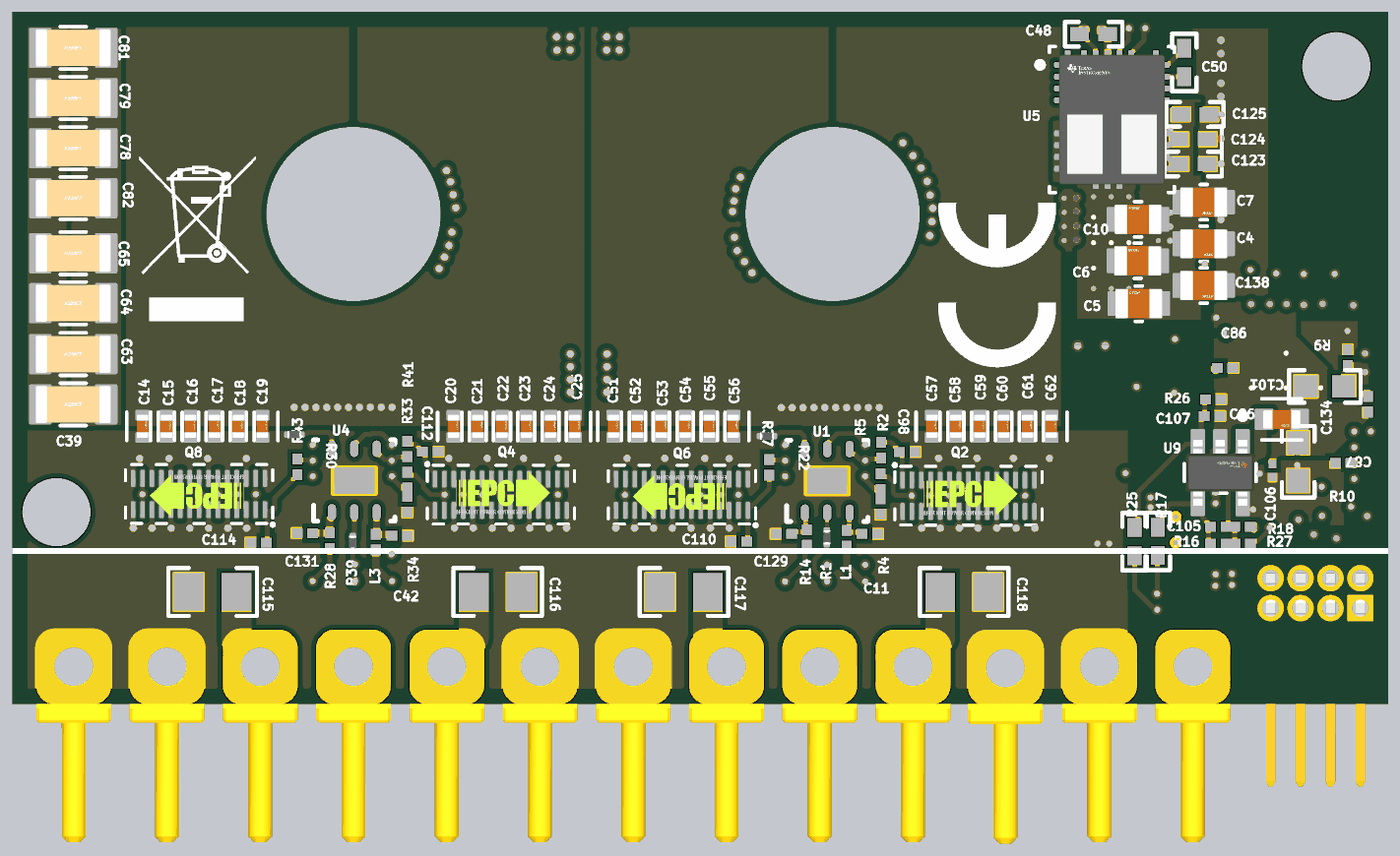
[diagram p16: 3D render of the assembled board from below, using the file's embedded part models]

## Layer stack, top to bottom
Top Solder: solder mask 0.4, Solder Resist, Dk 3.5
Top Layer: signal copper 2.4
Dielectric 1: prepreg 8, FR-4 High Tg, Dk 3.9
Layer 1: signal copper 3.6
Dielectric 2: core 6, FR-4 High Tg, Dk 3.9
Layer 2: signal copper 3.6
Dielectric 3: prepreg 6, FR-4 High Tg, Dk 3.9
Layer 3: signal copper 3.6
Dielectric 4: core 6, FR-4 High Tg, Dk 3.9
Layer 4: signal copper 3.6
Dielectric 5: prepreg 6, FR-4 High Tg, Dk 3.9
Layer 5: signal copper 3.6
Dielectric 6: core 6, FR-4 High Tg, Dk 3.9
Layer 6: signal copper 3.6
Dielectric 7: prepreg 6, FR-4 High Tg, Dk 3.9
Layer 7: signal copper 3.6
Dielectric 8: core 6, FR-4 High Tg, Dk 3.9
Layer 8: signal copper 3.6
Dielectric 9: prepreg 6, FR-4 High Tg, Dk 3.9
Layer 9: signal copper 3.6
Dielectric 10: core 6, FR-4 High Tg, Dk 3.9
Layer 10: signal copper 3.6
Dielectric 11: prepreg 6, FR-4 High Tg, Dk 3.9
Layer 11: signal copper 3.6
Dielectric 12: core 6, FR-4 High Tg, Dk 3.9
Layer 12: signal copper 3.6
Dielectric 13: prepreg 8, FR-4 High Tg, Dk 3.9
Bottom Layer: signal copper 2.4
Bottom Solder: solder mask 0.4, Solder Resist, Dk 3.5

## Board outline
0,0 2299.21,0 2299.21,1157.48 0,1157.48
cut-out: 928.35,673.7 cw(c928.35,819.37) 782.68,819.37 cw(c928.35,819.37) 928.35,965.04 cw(c928.35,819.37) 1074.02,819.37 cw(c928.35,819.37)
cut-out: 1729.14,673.7 cw(c1729.14,819.37) 1583.47,819.37 cw(c1729.14,819.37) 1729.14,965.04 cw(c1729.14,819.37) 1874.81,819.37 cw(c1729.14,819.37)

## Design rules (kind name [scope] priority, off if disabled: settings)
AcuteAngle [All] p1: minimum=4.50000000000000E+0001 checktracksonly=FALSE
AssemblyTestPointUsage [All] p1: valid=2
BoardOutlineClearance BoardOutlineClearance_MountingHoles [OnCopper and InComponentClass('Mounting Holes')] p1: gap=39.37 ignorepadtopadclearanceinfootprint=FALSE
BoardOutlineClearance BoardOutlineClearance_Poly [OnCopper and IsPoly] p2: gap=25 ignorepadtopadclearanceinfootprint=FALSE
BoardOutlineClearance [OnCopper and Not InComponentClass('Logo') and not InComponentClass('FiducialMark') and not InRegion(1000,500,4000,800) and not InPoly] p3: gap=25 ignorepadtopadclearanceinfootprint=FALSE except(10: THPad-OutlineEdge THPad-CutoutEdge Via-OutlineEdge Via-CutoutEdge)
Clearance Clearance_Keepouts [((IsTrack Or IsArc) And Not InPoly) And IsFree and IsKeepOut vs ((IsTrack Or IsArc) And Not InPoly) And IsFree and IsKeepOut] p1: gap=0 ignorepadtopadclearanceinfootprint=FALSE
Clearance Clearance_Poly [InPolygon] p2: gap=8 ignorepadtopadclearanceinfootprint=TRUE
Clearance Clearance_FiducialMark [IsKeepOut and InComponentClass('FiducialMark') vs IsPad and InComponentClass('FiducialMark')] p3: gap=0 ignorepadtopadclearanceinfootprint=FALSE
Clearance [All] p4: gap=6 ignorepadtopadclearanceinfootprint=TRUE
ComponentClearance ComponentClearance_MountingHoles_FiducialMarks [InComponentClass('Mounting Holes') vs InComponentClass('FiducialMark')] p1: gap=50 collisioncheckmode=3 verticalgap=10 showdistances=FALSE
ComponentClearance ComponentClearance_Shunt [InComponentClass('Header') vs InComponentClass('Shunt')] p2: gap=0 collisioncheckmode=3 verticalgap=0 showdistances=FALSE
ComponentClearance ComponentClearance_Logo [InComponentClass('Logo')] p3: gap=30 collisioncheckmode=3 verticalgap=10 showdistances=FALSE
ComponentClearance ComponentClearance_ScrewToNut [(HasFootprint('NY PMS 440 0025 PH')) vs (HasFootprint('Keystone_1902C'))] p4: gap=5 collisioncheckmode=3 verticalgap=10 showdistances=FALSE
ComponentClearance ComponentClearance_MountingHoles [InComponentClass('Mounting Holes')] p5: gap=100 collisioncheckmode=3 verticalgap=100000 showdistances=FALSE
ComponentClearance ComponentClearance_SmallPassives [HasFootprint('0201*') or HasFootprint('0402*') or HasFootprint('0508') or HasFootprint('0603*') or HasFootprint('0612') or HasFootprint('0805*') or HasFootprint('0815*') or HasFootprint('0830*') or HasFootprint('1206*') or HasFootprint('1210*') or HasFootprint('1808*') or HasFootprint('1812*') or HasFootprint('1825*') or HasFootprint('2010*') or HasFootprint('2220*') or HasFootprint('2225*') or HasFootprint('2512*') or HasFootprint('2728*') or HasFootprint('3518*') vs HasFootprint('0201*') or HasFootprint('0402*') or HasFootprint('0508') or HasFootprint('0603*') or HasFootprint('0612') or HasFootprint('0805*') or HasFootprint('0815*') or HasFootprint('0830*') or HasFootprint('1206*') or HasFootprint('1210*') or HasFootprint('1808*') or HasFootprint('1812*') or HasFootprint('1825*') or HasFootprint('2010*') or HasFootprint('2220*') or HasFootprint('2225*') or HasFootprint('2512*') or HasFootprint('2728*') or HasFootprint('3518*')] p6: gap=14.96 collisioncheckmode=3 verticalgap=10 showdistances=FALSE
ComponentClearance ComponentClearance_THtoSMT [IsThruComponent vs IsSMTComponent] p7: gap=30 collisioncheckmode=3 verticalgap=30 showdistances=FALSE
ComponentClearance ComponentClearance_THtoTH [IsThruComponent vs IsThruComponent] p8: gap=20 collisioncheckmode=3 verticalgap=30 showdistances=FALSE
ComponentClearance [All] p9: gap=20 collisioncheckmode=3 verticalgap=10 showdistances=FALSE
DiffPairsRouting [All] p1: maxlimit=100 minlimit=10 mostfreqgap=10 toplayer_minwidth=15 toplayer_maxwidth=15 toplayer_prefwidth=15 midlayer1_minwidth=15 midlayer1_maxwidth=15 midlayer1_prefwidth=15 midlayer2_minwidth=15 midlayer2_maxwidth=15 midlayer2_prefwidth=15 midlayer3_minwidth=15 midlayer3_maxwidth=15 midlayer3_prefwidth=15 midlayer4_minwidth=15 midlayer4_maxwidth=15 midlayer4_prefwidth=15 midlayer5_minwidth=15 midlayer5_maxwidth=15 midlayer5_prefwidth=15 midlayer6_minwidth=15 midlayer6_maxwidth=15 midlayer6_prefwidth=15 midlayer7_minwidth=15 midlayer7_maxwidth=15 midlayer7_prefwidth=15 midlayer8_minwidth=15 midlayer8_maxwidth=15 midlayer8_prefwidth=15 midlayer9_minwidth=15 midlayer9_maxwidth=15 midlayer9_prefwidth=15 midlayer10_minwidth=15 midlayer10_maxwidth=15 midlayer10_prefwidth=15 midlayer11_minwidth=15 midlayer11_maxwidth=15 midlayer11_prefwidth=15 midlayer12_minwidth=15 midlayer12_maxwidth=15 midlayer12_prefwidth=15 bottomlayer_minwidth=15 bottomlayer_maxwidth=15 bottomlayer_prefwidth=15 maxuncoupledlength=1000
FabricationTestPointUsage TestPointUsage [All] p1: valid=2 allowmultiple=FALSE
FabricationTestpoint Testpoint [All] p1: side=3 testpointundercomponent=TRUE minsize=40 maxsize=100 preferedsize=60 minholesize=0 maxholesize=40 preferedholesize=32 testpointgrid=1 allowsidetop=TRUE allowsidebottom=TRUE usegrid=TRUE gridtolerance=0.01
FanoutControl Fanout_LCC [IsLCC] p1: bgadir=Out bgaviamode=Centered fanoutstyle=Auto fanoutdirection=Alternating viagrid=1 // Fanout_LCC (Default Rule)
FanoutControl Fanout_BGA [IsBGA] p2: bgadir=Out bgaviamode=Centered fanoutstyle=Auto fanoutdirection=Alternating viagrid=1 // Fanout_BGA (Default Rule)
FanoutControl Fanout_Default [All] p4: bgadir=Out bgaviamode=Centered fanoutstyle=Auto fanoutdirection=Alternating viagrid=1 // Fanout_Default (Default Rule)
FanoutControl Fanout_Small [(CompPinCount < 5)] p5: bgadir=Out bgaviamode=Centered fanoutstyle=Auto fanoutdirection=OutThenIn viagrid=1 // Fanout_Small (Default Rule)
HoleSize [All] p1: absolutevalues=TRUE maxlimit=251 minlimit=7.87 maxpercent=80.000 minpercent=20.000
MinimumAnnularRing MinimumAnnularRing_ThermalPadVias [IsVia and InAnyComponent] p1: minimumring=5.91
MinimumAnnularRing [All] p2: minimumring=4
MinimumSolderMaskSliver MinimumSolderMaskSliver_Logo [InComponentClass('Logo') vs InComponentClass('Logo')] p1: minsoldermaskwidth=0.7
MinimumSolderMaskSliver [All] p2: minsoldermaskwidth=3.94
PlaneConnect [All] p1: planeconnectstyle=Relief reliefexpansion=10 reliefentries=4 reliefconductorwidth=10 reliefairgap=10
PolygonConnect [All] p1: connectstyle=Direct reliefconductorwidth=10 reliefentries=4 polygonreliefangle="90 Angle" airgapwidth=10
RoutingVias ThermalPadVias [IsVia and InAnyComponent] p1: holewidth=7.87 width=19.68 viastyle="Through Hole" minholewidth=7.87 minwidth=19.68 maxholewidth=12.99 maxwidth=23.62
RoutingVias [All] p2: holewidth=16 width=34 viastyle="Through Hole" minholewidth=7.87 minwidth=24 maxholewidth=40 maxwidth=65
SilkToBoardRegionClearance [Not ((IsComment or IsDesignator) And (Hide <> 'False')) and not InRegion(1000,500,4000,800)] p1:
SilkToSilkClearance SilkToSilkClearance_Pb-FreeLogo [(HasFootprint('Pb-Free_Overlay_Medium') OR HasFootprint('Pb-Free_Overlay_Small')) vs (HasFootprint('Pb-Free_Overlay_Medium') OR HasFootprint('Pb-Free_Overlay_Small'))] p1: silktosilkclearance=0
SilkToSilkClearance [All] p2: silktosilkclearance=3.94
SilkToSolderMaskClearance SilkToComponentPadClearance [(IsPad or IsFill or IsRegion) and InAnycomponent] p1: minsilkscreentomaskgap=5 clearancetoexposedcopper=TRUE
SilkToSolderMaskClearance "Silk to Solder Mask Opening" [All] p2: minsilkscreentomaskgap=3.94 clearancetoexposedcopper=FALSE
SolderMaskExpansion [All] p1: expansion=1.97 istentingtop=FALSE
UnRoutedNet [All] p1: checkbadconnections=TRUE
Width [All] p1: maxlimit=100 minlimit=6 preferedwidth=10
14 further rules are at their usual default settings.

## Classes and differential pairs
component class PMP23340E3_C2K_Control: C83 C84 C85 C86 C87 C88 C89 C90 C91 C92 C93 C94 C95 C96 C100 C101 C103 C104 C105 C106 C107 C108 C109 C133 C134 C135 C136 R9 R10 R11 R12 R13 R16 R17 R18 R20 R21 R23 R24 R25 R26 R27 R31 R32 RT1 RT2 U7 U8 U9
component class PMP23340E3_C2K_Power_Stage: C1 C2 C3 C4 C5 C6 C7 C8 C9 C10 C11 C12 C13 C14 C15 C16 C17 C18 C19 C20 C21 C22 C23 C24 C25 C26 C27 C28 C29 C30 C31 C32 C33 C34 C35 C36 C37 C38 C39 C40 C41 C42 C43 C44 C45 C46 C47 C48 C49 C50 C51 C52 C53 C54 C55 C56 C57 C58 C59 C60 C61 C62 C63 C64 C65 C66 C67 C68 C69 C70 C71 C72 C73 C74 C75 C76 C77 C78 C79 C80 C81 C82 C97 C98 C99 C110 C111 C112 C113 C114 C115 C116 C117 C118 C119 C120 C121 C122 C123 C124 C125 C126 C127 C128 C129 C130 C131 C132 C137 C138 Gnd1 Gnd2 Gnd3 Gnd4 Gnd5 Gnd6 J1 L1 L2 L3 L4 NT1 Q1 Q2 Q3 Q4 Q5 Q6 Q7 Q8 R1 R2 R3 R4 R5 R6 R7 R8 R14 R15 R19 R22 R28 R29 R30 R33 R34 R35 R36 R37 R38 R39 R40 R41 R42 R43 R44 R45 TP1 TP2 TP3 TP4 TP5 TP6 TP7 TP8 TP9 TP12 TP13 TP14 TP15 U1 U2 U3 U4 U5 U6 Vin1 Vout1 Vout2 Vout3 Vout4 Vout5 Vout6
component class AssemblyNote: ZZ1 ZZ2 ZZ3 ZZ4
component class PMP23340E3_C2K_Hardware: Logo1 Logo2 Logo3 Logo4 ZZ1 ZZ2 ZZ3 ZZ4
component class Logo: Logo2

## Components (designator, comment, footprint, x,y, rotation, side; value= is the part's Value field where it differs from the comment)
C1 "C2012X5R2A475K125AC" FP-C2012X5R2A475K125AC_0805-MFG 298.23,957.68 r0 top value=4.7µF
C2 "C2012X5R2A475K125AC" FP-C2012X5R2A475K125AC_0805-MFG 308.58,1027.46 r0 top value=4.7µF
C3 "C2012X5R2A475K125AC" FP-C2012X5R2A475K125AC_0805-MFG 308.13,1097.43 r0 top value=4.7µF
C4 "C2012X5R2A475K125AC" FP-C2012X5R2A475K125AC_0805-MFG 308.07,769.68 r0 bottom value=4.7µF
C5 "C2012X5R2A475K125AC" FP-C2012X5R2A475K125AC_0805-MFG 416.61,669.46 r180 bottom value=4.7µF
C6 "C2012X5R2A475K125AC" FP-C2012X5R2A475K125AC_0805-MFG 418.31,741.14 r180 bottom value=4.7µF
C7 "C2012X5R2A475K125AC" FP-C2012X5R2A475K125AC_0805-MFG 417.87,810.48 r180 bottom value=4.7µF
C8 "C2012X5R2A475K125AC" FP-C2012X5R2A475K125AC_0805-MFG 415.39,917 r180 top value=4.7µF
C9 "C2012X5R2A475K125AC" FP-C2012X5R2A475K125AC_0805-MFG 414.9,986.57 r180 top value=4.7µF
C10 "C2012X5R2A475K125AC" FP-C2012X5R2A475K125AC_0805-MFG 308.11,839.19 r0 bottom value=4.7µF
C11 "GRM033R61A105ME15D" 0201 866.14,284.45 r180 bottom value=1uF
C12 "160R07X104KV4T" 0402_065 495.66,612.06 r180 top value=0.1uF
C13 "160R07X104KV4T" 0402_065 340.48,684.49 r270 top value=0.1uF
C14 "GRM155C81C225ME15D" FP-GRM155C81C225ME15D_0402-MFG 2081.83,464.29 r90 bottom value=2.2µF
C15 "GRM155C81C225ME15D" FP-GRM155C81C225ME15D_0402-MFG 2041.77,464.29 r90 bottom value=2.2µF
C16 "GRM155C81C225ME15D" FP-GRM155C81C225ME15D_0402-MFG 2001.71,464.29 r90 bottom value=2.2µF
C17 "GRM155C81C225ME15D" FP-GRM155C81C225ME15D_0402-MFG 1961.65,464.29 r90 bottom value=2.2µF
C18 "GRM155C81C225ME15D" FP-GRM155C81C225ME15D_0402-MFG 1921.59,464.29 r90 bottom value=2.2µF
C19 "GRM155C81C225ME15D" FP-GRM155C81C225ME15D_0402-MFG 1881.54,464.29 r90 bottom value=2.2µF
C20 "GRM155C81C225ME15D" FP-GRM155C81C225ME15D_0402-MFG 1561.98,464.1 r90 bottom value=2.2µF
C21 "GRM155C81C225ME15D" FP-GRM155C81C225ME15D_0402-MFG 1521.4,464.1 r90 bottom value=2.2µF
C22 "GRM155C81C225ME15D" FP-GRM155C81C225ME15D_0402-MFG 1480.81,464.1 r90 bottom value=2.2µF
C23 "GRM155C81C225ME15D" FP-GRM155C81C225ME15D_0402-MFG 1440.23,464.1 r90 bottom value=2.2µF
C24 "GRM155C81C225ME15D" FP-GRM155C81C225ME15D_0402-MFG 1399.64,464.1 r90 bottom value=2.2µF
C25 "GRM155C81C225ME15D" FP-GRM155C81C225ME15D_0402-MFG 1359.06,464.1 r90 bottom value=2.2µF
C26 "GRM155C81C225ME15D" FP-GRM155C81C225ME15D_0402-MFG 1398.7,463.73 r90 top value=2.2µF
C27 "GRM155C81C225ME15D" FP-GRM155C81C225ME15D_0402-MFG 1439.05,463.73 r90 top value=2.2µF
C28 "GRM155C81C225ME15D" FP-GRM155C81C225ME15D_0402-MFG 1479.41,463.73 r90 top value=2.2µF
C29 "GRM155C81C225ME15D" FP-GRM155C81C225ME15D_0402-MFG 1519.76,463.73 r90 top value=2.2µF
C30 "GRM155C81C225ME15D" FP-GRM155C81C225ME15D_0402-MFG 1560.12,463.73 r90 top value=2.2µF
C31 "GRM155C81C225ME15D" FP-GRM155C81C225ME15D_0402-MFG 1600.47,463.73 r90 top value=2.2µF
C32 "GRM155C81C225ME15D" FP-GRM155C81C225ME15D_0402-MFG 1893,465.11 r90 top value=2.2µF
C33 "GRM155C81C225ME15D" FP-GRM155C81C225ME15D_0402-MFG 1933.15,465.11 r90 top value=2.2µF
C34 "GRM155C81C225ME15D" FP-GRM155C81C225ME15D_0402-MFG 1973.31,465.11 r90 top value=2.2µF
C35 "GRM155C81C225ME15D" FP-GRM155C81C225ME15D_0402-MFG 2013.47,465.11 r90 top value=2.2µF
C36 "GRM155C81C225ME15D" FP-GRM155C81C225ME15D_0402-MFG 2053.63,465.11 r90 top value=2.2µF
C37 "GRM155C81C225ME15D" FP-GRM155C81C225ME15D_0402-MFG 2093.78,465.11 r90 top value=2.2µF
C38 "GRM033R61A105ME15D" 0201 1008.35,284.07 r0 top value=1uF
C39 "C1206C224K3JAC7800" FP-C1206C224K3JAC7800_1206-MFG 2197.6,500.99 r180 bottom value=220nF
C40 "C1206C224K3JAC7800" FP-C1206C224K3JAC7800_1206-MFG 2192.68,501.56 r180 top value=220nF
C41 "C1206C224K3JAC7800" FP-C1206C224K3JAC7800_1206-MFG 2192.68,840.51 r180 top value=220nF
C42 "GRM033R61A105ME15D" 0201 1651.82,281.49 r180 bottom value=1uF
C43 "C1206C224K3JAC7800" FP-C1206C224K3JAC7800_1206-MFG 2192.68,755.5 r180 top value=220nF
C44 "C1206C224K3JAC7800" FP-C1206C224K3JAC7800_1206-MFG 2192.68,672.14 r180 top value=220nF
C45 "C1206C224K3JAC7800" FP-C1206C224K3JAC7800_1206-MFG 2192.68,586.83 r180 top value=220nF
C46 "C1206C224K3JAC7800" FP-C1206C224K3JAC7800_1206-MFG 2192.68,1093.47 r180 top value=220nF
C47 "C1206C224K3JAC7800" FP-C1206C224K3JAC7800_1206-MFG 2192.68,1009.65 r180 top value=220nF
C48 "160R07X104KV4T" 0402_065 492.13,1120.08 r180 bottom value=0.1uF
C49 "C1206C224K3JAC7800" FP-C1206C224K3JAC7800_1206-MFG 2192.68,924.47 r180 top value=220nF
C50 "160R07X104KV4T" 0402_065 340.55,1072.83 r90 bottom value=0.1uF
C51 "GRM155C81C225ME15D" FP-GRM155C81C225ME15D_0402-MFG 1294.45,464.29 r90 bottom value=2.2µF
C52 "GRM155C81C225ME15D" FP-GRM155C81C225ME15D_0402-MFG 1254.47,464.29 r90 bottom value=2.2µF
C53 "GRM155C81C225ME15D" FP-GRM155C81C225ME15D_0402-MFG 1214.48,464.29 r90 bottom value=2.2µF
C54 "GRM155C81C225ME15D" FP-GRM155C81C225ME15D_0402-MFG 1174.5,464.29 r90 bottom value=2.2µF
C55 "GRM155C81C225ME15D" FP-GRM155C81C225ME15D_0402-MFG 1134.52,464.29 r90 bottom value=2.2µF
C56 "GRM155C81C225ME15D" FP-GRM155C81C225ME15D_0402-MFG 1094.54,464.29 r90 bottom value=2.2µF
C57 "GRM155C81C225ME15D" FP-GRM155C81C225ME15D_0402-MFG 762.29,464.29 r90 bottom value=2.2µF
C58 "GRM155C81C225ME15D" FP-GRM155C81C225ME15D_0402-MFG 722.34,464.29 r90 bottom value=2.2µF
C59 "GRM155C81C225ME15D" FP-GRM155C81C225ME15D_0402-MFG 682.4,464.29 r90 bottom value=2.2µF
C60 "GRM155C81C225ME15D" FP-GRM155C81C225ME15D_0402-MFG 642.45,464.29 r90 bottom value=2.2µF
C61 "GRM155C81C225ME15D" FP-GRM155C81C225ME15D_0402-MFG 602.51,464.29 r90 bottom value=2.2µF
C62 "GRM155C81C225ME15D" FP-GRM155C81C225ME15D_0402-MFG 562.56,464.29 r90 bottom value=2.2µF
C63 "C1206C224K3JAC7800" FP-C1206C224K3JAC7800_1206-MFG 2197.6,585.04 r180 bottom value=220nF
C64 "C1206C224K3JAC7800" FP-C1206C224K3JAC7800_1206-MFG 2197.6,670.35 r180 bottom value=220nF
C65 "C1206C224K3JAC7800" FP-C1206C224K3JAC7800_1206-MFG 2197.6,753.71 r180 bottom value=220nF
C66 "GRM155C81C225ME15D" FP-GRM155C81C225ME15D_0402-MFG 582.82,464.74 r90 top value=2.2µF
C67 "GRM155C81C225ME15D" FP-GRM155C81C225ME15D_0402-MFG 623.11,464.74 r90 top value=2.2µF
C68 "GRM155C81C225ME15D" FP-GRM155C81C225ME15D_0402-MFG 663.39,464.74 r90 top value=2.2µF
C69 "GRM155C81C225ME15D" FP-GRM155C81C225ME15D_0402-MFG 703.68,464.74 r90 top value=2.2µF
C70 "GRM155C81C225ME15D" FP-GRM155C81C225ME15D_0402-MFG 743.97,464.74 r90 top value=2.2µF
C71 "GRM155C81C225ME15D" FP-GRM155C81C225ME15D_0402-MFG 784.26,464.74 r90 top value=2.2µF
C72 "GRM155C81C225ME15D" FP-GRM155C81C225ME15D_0402-MFG 1102.36,464.16 r90 top value=2.2µF
C73 "GRM155C81C225ME15D" FP-GRM155C81C225ME15D_0402-MFG 1142.52,464.16 r90 top value=2.2µF
C74 "GRM155C81C225ME15D" FP-GRM155C81C225ME15D_0402-MFG 1182.67,464.16 r90 top value=2.2µF
C75 "GRM155C81C225ME15D" FP-GRM155C81C225ME15D_0402-MFG 1222.83,464.16 r90 top value=2.2µF
C76 "GRM155C81C225ME15D" FP-GRM155C81C225ME15D_0402-MFG 1262.99,464.16 r90 top value=2.2µF
C77 "GRM155C81C225ME15D" FP-GRM155C81C225ME15D_0402-MFG 1303.15,464.16 r90 top value=2.2µF
C78 "C1206C224K3JAC7800" FP-C1206C224K3JAC7800_1206-MFG 2197.6,929.47 r180 bottom value=220nF
C79 "C1206C224K3JAC7800" FP-C1206C224K3JAC7800_1206-MFG 2197.6,1013.43 r180 bottom value=220nF
C80 "GRM033R61A105ME15D" 0201 1810.79,283.29 r0 top value=1uF
C81 "C1206C224K3JAC7800" FP-C1206C224K3JAC7800_1206-MFG 2197.6,1097.25 r180 bottom value=220nF
C82 "C1206C224K3JAC7800" FP-C1206C224K3JAC7800_1206-MFG 2197.6,845.87 r180 bottom value=220nF
C83 "GRM033R61A105ME15D" 0201 380,360.1 r180 top value=1uF
C84 "GRM033R61A105ME15D" 0201 285.71,300.03 r270 top value=1uF
C85 "GRM033R61E103KA12D" 0201_033 192.42,336.17 r270 top value=0.01uF
C86 "GRM0335C1H100JA01D" 0201_033 272.34,561.83 r180 bottom value=10pF
C87 "GRM0335C1H100JA01D" 0201_033 33.37,501.23 r270 bottom value=10pF
C88 "GRM033R71C222KA88D" 0201 60.95,682.23 r270 top value=2200pF
C89 "GRM033R71C222KA88D" 0201 141.38,682.23 r270 top value=2200pF
C90 "GJM0335C1E100JB01D" 0201 80.1,347.14 r270 top value=10pF
C91 "GJM0335C1E100JB01D" 0201 296.32,622.1 r90 top value=10pF
C92 "GRM0335C1H100JA01D" 0201_033 383.7,605.94 r90 top value=10pF
C93 "GRM0335C1H100JA01D" 0201_033 386.52,544.27 r270 top value=10pF
C94 "GRM0335C1H100JA01D" 0201_033 320.49,473.66 r270 top value=10pF
C95 "GRM0335C1H100JA01D" 0201_033 325.78,612.21 r90 top value=10pF
C96 "CC0603KRX5R6BB106" FP-CC0603KRX5R6BB106_0603-MFG 177.54,475.91 r0 bottom value=10µF
C97 "GRM0335C1H100JA01D" 0201_033 847.46,339.1 r90 top value=10pF
C98 "GRM0335C1H100JA01D" 0201_033 803.72,421.51 r180 bottom value=10pF
C99 "GRM0335C1H100JA01D" 0201_033 1067.91,422.24 r180 top value=10pF
C100 "GRM033Z71C104KE14D" 0201 254.92,403.54 r0 top value=0.1uF
C101 "GRM188R61A225KE34D" 0603 105.77,531.09 r0 bottom value=2.2uF
C103 "GRM033R71C102KA01D" 0201 229.12,682.23 r270 top value=1000pF
C104 "GRM033R71C102KA01D" 0201 197.97,682.23 r270 top value=1000pF
C105 "CGA1A2X7R1H221K030BA" 0201_033 283.46,296.37 r0 bottom value=220pF
C106 "ATC530Z104KT10T" 0201_033L 193.11,390.35 r90 bottom value=0.1uF
C107 "CGA1A2X7R1H221K030BA" 0201_033 294.14,481.45 r0 bottom value=220pF
C108 "GRM033R71C102KA01D" 0201 169.33,682.23 r270 top value=1000pF
C109 "GRM033R71C102KA01D" 0201 110.23,682.23 r270 top value=1000pF
C110 "GRM0335C1H100JA01D" 0201_033 1084.88,271.7 r0 bottom value=10pF
C111 "GRM0335C1H100JA01D" 0201_033 1632.87,336.61 r90 top value=10pF
C112 "GRM0335C1H100JA01D" 0201_033 1600.87,422.04 r180 bottom value=10pF
C113 "GRM0335C1H100JA01D" 0201_033 1859.25,423.23 r180 top value=10pF
C114 "GRM0335C1H100JA01D" 0201_033 1887.59,269.57 r0 bottom value=10pF
C115 "GRT21BR61E226ME13L" 0805_HV 1964.62,187.39 r0 bottom value=22uF
C116 "GRT21BR61E226ME13L" 0805_HV 1488.25,187.39 r180 bottom value=22uF
C117 "GRT21BR61E226ME13L" 0805_HV 1176.87,187.39 r0 bottom value=22uF
C118 "GRT21BR61E226ME13L" 0805_HV 708.49,187.39 r180 bottom value=22uF
C119 "GRT21BR61E226ME13L" 0805_HV 1183.09,187.39 r0 top value=22uF
C120 "GRT21BR61E226ME13L" 0805_HV 718.95,187.39 r180 top value=22uF
C121 "GRT21BR61E226ME13L" 0805_HV 1495.72,187.39 r180 top value=22uF
C122 "GRT21BR61E226ME13L" 0805_HV 1959.87,187.39 r0 top value=22uF
C123 "GRM155R62A104KE14D" 0402 325.71,903 r180 bottom value=0.1uF
C124 "GRM155R62A104KE14D" 0402 325.71,944.47 r180 bottom value=0.1uF
C125 "GRM155R62A104KE14D" 0402 322.83,986.22 r180 bottom value=0.1uF
C126 "GRM155R62A104KE14D" 0402 331.19,901.24 r180 top value=0.1uF
C127 "GRM155R62A104KE14D" 0402 331.19,854.89 r180 top value=0.1uF
C128 "GRM155R62A104KE14D" 0402 331.19,808.54 r180 top value=0.1uF
C129 "GRM0335C1H100JA01D" 0201_033 1009.84,284.45 r180 bottom value=10pF
C130 "GRM0335C1H100JA01D" 0201_033 856.91,284.07 r0 top value=10pF
C131 "GRM0335C1H100JA01D" 0201_033 1810.36,285.63 r180 bottom value=10pF
C132 "GRM0335C1H100JA01D" 0201_033 1642.33,285.6 r0 top value=10pF
C133 "GRM033Z71C104KE14D" 0201 44.08,571.17 r90 top value=0.1uF
C134 "GRM187R61A226ME15D" 0603 150.15,404.91 r90 bottom value=22uF
C135 "GRM033Z71C104KE14D" 0201 228.29,372.67 r0 top value=0.1uF
C136 "GRM033Z71C104KE14D" 0201 258.69,682.21 r90 top value=0.1uF
C137 "C2012X5R2A475K125AC" FP-C2012X5R2A475K125AC_0805-MFG 415.83,1055.96 r180 top value=4.7µF
C138 "C2012X5R2A475K125AC" FP-C2012X5R2A475K125AC_0805-MFG 308.07,699.8 r0 bottom value=4.7µF
Gnd1 "3621-0-32-15-00-00-08-0" Mill-Max_3621-0-32-xx-00-00-08-0 482.16,-32.19 r0 top
Gnd2 "3621-0-32-15-00-00-08-0" Mill-Max_3621-0-32-xx-00-00-08-0 1417.4,-32.19 r0 top
Gnd3 "3621-0-32-15-00-00-08-0" Mill-Max_3621-0-32-xx-00-00-08-0 2040.89,-32.19 r0 top
Gnd4 "3621-0-32-15-00-00-08-0" Mill-Max_3621-0-32-xx-00-00-08-0 639.63,-34.58 r0 top
Gnd5 "3621-0-32-15-00-00-08-0" Mill-Max_3621-0-32-xx-00-00-08-0 1261.53,-32.19 r0 top
Gnd6 "3621-0-32-15-00-00-08-0" Mill-Max_3621-0-32-xx-00-00-08-0 2196.77,-32.19 r0 top
J1 "ASP-231707-01" FP-FTSH-104-04-L-D-RA_HDR8-MFG 121.2,60.86 r0 top
L1 "BLM03AX241SN1D" 0201_033 904.71,276.99 r90 bottom
L2 "BLM03AX241SN1D" 0201_033 970.05,278.02 r90 top
L3 "BLM03AX241SN1D" 0201_033 1691.8,270.46 r90 bottom
L4 "BLM03AX241SN1D" 0201_033 1765.81,271.77 r90 top
Logo1 "CE Mark" CE_Mark_5mm 653.3,700.83 r90 bottom
Logo2 "Texas Instruments" TI_Symbol_Overlay_Small 706.67,1050.19 r0 top
Logo3 "FCC disclaimer" FCC_disclaimer 777.73,3884.85 r0 top
Logo4 "WEEE logo" WEEE_Minimum 1991.82,812.47 r180 bottom
NT1 "Net-Tie" NetTie_0402 398.08,214.02 r180 top net-tie
Q1 "EPC2066" D0650#1 701.37,348.25 r180 top
Q2 "EPC2066" D0650#2 701.37,348.25 r180 bottom
Q3 "EPC2066" D0650#1 1180.13,349.64 r0 top
Q4 "EPC2066" D0650#2 1180.22,349.96 r0 bottom
Q5 "EPC2066" D0650#1 1482.8,349.96 r180 top
Q6 "EPC2066" D0650#2 1482.8,349.96 r180 bottom
Q7 "EPC2066" D0650#1 1987.25,351.07 r0 top
Q8 "EPC2066" D0650#2 1987.25,351.07 r0 bottom
R1 "RC0201JR-070RL" "FP-RC0201JR-070RL_0201 (0603 Metric)-IPC_C" 937.99,278.54 r90 bottom
R2 "RC0201JR-0710RL" 0201 848.29,371.7 r90 bottom value=10
R3 "RC0201FS-7D2RL" 0201 847.46,379.3 r90 top value=2.00
R4 "RC0201DR-075K11L" 0201 848.29,330.36 r90 bottom value=5.11k
R5 "RC0201FS-7D2RL" 0201 847.6,424.29 r90 bottom value=2.00
R6 "RC0201JR-0710RL" 0201 1032.41,353.55 r90 top value=10
R7 "RC0201FS-7D2RL" 0201 1033.45,411.01 r270 top value=2.00
R8 "RC0201DR-075K11L" 0201 1086.78,275.04 r180 top value=5.11k
R9 "RC0201FR-071RL" 0201 67.18,578.94 r270 bottom value=1.00
R10 "CRCW02012K20FKED" 0201 74.96,403.39 r0 bottom value=2.20k
R11 "RC0201JR-070RL" "FP-RC0201JR-070RL_0201 (0603 Metric)-IPC_C" 310.53,435.36 r180 top
R12 "CRCW02012K20FKED" 0201 287.44,686.03 r90 top value=2.20k
R13 "RG1005P-104-B-T5" 0402 157.78,320.17 r270 top value=100k
R14 "CRCW020120R0FNED" 0201_033 971.46,278.54 r90 bottom value=20.0
R15 "CRCW020120R0FNED" 0201_033 900.59,277.56 r90 top value=20.0
R16 "RC0201FS-7D1KL" 0201 283.46,267.72 r0 bottom value=1.00k
R17 "RC0402FR-0714KL" 0402 384.8,271.89 r90 bottom value=14.0k
R18 "RC0201FS-7D24R3L" 0201 243.32,296.37 r180 bottom value=24.3
R19 "RC0201JR-070RL" "FP-RC0201JR-070RL_0201 (0603 Metric)-IPC_C" 842.4,447.69 r0 top
R20 "RC0201JR-7D10KL" 0201 123.97,297.73 r270 top value=10k
R21 "ERJ-2RKF1503X" 0402 65.89,275.89 r0 top value=150k
R22 "RC0201JR-070RL" "FP-RC0201JR-070RL_0201 (0603 Metric)-IPC_C" 1038.06,447.94 r180 bottom
R23 "RC0201FR-072K8L" 0201 89.57,310.04 r0 top value=2.80k
R24 "RC0201FR-078K66L" 0201 48.12,310.32 r180 top value=8.66k
R25 "RC0402FR-0714KL" 0402 423.64,271.43 r90 bottom value=14.0k
R26 "RC0201FS-7D1KL" 0201 292.41,509.5 r0 bottom value=1.00k
R27 "RC0201FR-075K11L" 0201 243,267.88 r180 bottom value=5.11k
R28 "CRCW020120R0FNED" 0201_033 1769,273.22 r90 bottom value=20.0
R29 "CRCW020120R0FNED" 0201_033 1693.21,277.12 r90 top value=20.0
R30 "RC0201JR-070RL" "FP-RC0201JR-070RL_0201 (0603 Metric)-IPC_C" 1827.97,450.52 r180 bottom
R31 "RC0201JS-7D10KL" 0201 287.64,726.21 r270 top value=10k
R32 "RC0201JS-7D10KL" 0201 380,388.64 r180 top value=10k
R33 "RC0201JR-0710RL" 0201 1639.2,374.45 r90 bottom value=10
R34 "RC0201DR-075K11L" 0201 1639.2,334.1 r90 bottom value=5.11k
R35 "RC0201JR-0710RL" 0201 1823.11,353.55 r90 top value=10
R36 "RC0201DR-075K11L" 0201 1887.66,273.99 r180 top value=5.11k
R37 "RC0201FS-7D2RL" 0201 1034.45,395.67 r270 bottom value=2.00
R38 "RC0201JR-070RL" "FP-RC0201JR-070RL_0201 (0603 Metric)-IPC_C" 937.26,276.83 r90 top
R39 "RC0201JR-070RL" "FP-RC0201JR-070RL_0201 (0603 Metric)-IPC_C" 1730.4,269.09 r90 bottom
R40 "RC0201FS-7D2RL" 0201 1632.87,376.97 r90 top value=2.00
R41 "RC0201FS-7D2RL" 0201 1639.2,426.62 r90 bottom value=2.00
R42 "RC0201FS-7D2RL" 0201 1824.36,411.01 r270 top value=2.00
R43 "RC0201FS-7D2RL" 0201 1823.34,396.3 r270 bottom value=2.00
R44 "RC0201JR-070RL" "FP-RC0201JR-070RL_0201 (0603 Metric)-IPC_C" 1727.45,271.65 r90 top
R45 "RC0201JR-070RL" "FP-RC0201JR-070RL_0201 (0603 Metric)-IPC_C" 1642.19,458.56 r0 top
RT1 "TMP6131DECT" DEC0002A 335.5,753.13 r90 top
RT2 "TMP6131DECT" DEC0002A 525.89,342.39 r270 top
TP1 "TESTPOINT" TP_25MIL-SMT 930.79,520.92 r0 top
TP2 "TESTPOINT" TP_25MIL-SMT 2157,386.05 r90 top
TP3 "TESTPOINT" TP_25MIL-SMT 1332.21,279.47 r90 top
TP4 "TESTPOINT" TP_25MIL-SMT 1331.4,411.23 r90 top
TP5 "TESTPOINT" TP_25MIL-SMT 549.73,285.86 r90 top
TP6 "TESTPOINT" TP_25MIL-SMT 1743.76,522.51 r90 top
TP7 "TESTPOINT" TP_25MIL-SMT 2093.86,798.81 r90 top
TP8 "TESTPOINT" TP_25MIL-SMT 585.95,923.89 r90 top
TP9 "TESTPOINT" TP_25MIL-SMT 584.4,814.14 r90 top
TP12 "TESTPOINT" TP_25MIL-SMT 2005.61,253.7 r90 top
TP13 "TESTPOINT" TP_25MIL-SMT 669.76,253.7 r90 top
TP14 "TESTPOINT" TP_25MIL-SMT 1181.77,253.7 r90 top
TP15 "TESTPOINT" TP_25MIL-SMT 1450.48,253.7 r90 top
U1 "UCD7138DRS" DRS0006A#1 937.3,373.03 r90 bottom
U2 "LMG2100R044" RAR0016A-MFG 462.64,757.18 r180 top
U3 "UCD7138DRS" DRS0006A#2 937.01,373.03 r90 top
U4 "UCD7138DRS" DRS0006A#1 1727.87,373.66 r90 bottom
U5 "LMG2100R044" RAR0016A-MFG 461.61,977.36 r180 bottom
U6 "UCD7138DRS" DRS0006A#2 1727.87,373.66 r90 top
U7 "F2800157QRHBRQ1" RHB0032E-MFG 170.45,528.62 r270 top
U8 "TLV75533PDRVR" DRV0006A 354.9,291.31 r0 top
U9 "TLV365DBVR" DBV0005A-MFG 280.51,386.81 r270 bottom
Vin1 "3621-0-32-15-00-00-08-0" Mill-Max_3621-0-32-xx-00-00-08-0 326.29,-32.19 r0 top
Vout1 "3621-0-32-15-00-00-08-0" Mill-Max_3621-0-32-xx-00-00-08-0 1885.02,-32.19 r0 top
Vout2 "3621-0-32-15-00-00-08-0" Mill-Max_3621-0-32-xx-00-00-08-0 1573.27,-32.19 r0 top
Vout3 "3621-0-32-15-00-00-08-0" Mill-Max_3621-0-32-xx-00-00-08-0 1105.65,-32.19 r0 top
Vout4 "3621-0-32-15-00-00-08-0" Mill-Max_3621-0-32-xx-00-00-08-0 793.91,-32.19 r0 top
Vout5 "3621-0-32-15-00-00-08-0" Mill-Max_3621-0-32-xx-00-00-08-0 949.78,-32.19 r0 top
Vout6 "3621-0-32-15-00-00-08-0" Mill-Max_3621-0-32-xx-00-00-08-0 1729.15,-32.19 r0 top
ZZ1 "This Assembly Note is for PCB labels only" AssemblyNoteLabel 185,3938 r0 top
ZZ2 "These assemblies are ESD sensitive, ESD precautions shall be observed." AssemblyNote 185,3829.11 r0 top
ZZ3 "These assemblies must be clean and free from flux and all contaminants. Use of no clean flux is not acceptable." AssemblyNote 185,3740.56 r0 top
ZZ4 "These assemblies must comply with workmanship standards IPC-A-610 Class 2, unless otherwise specified." AssemblyNote 185,3652 r0 top

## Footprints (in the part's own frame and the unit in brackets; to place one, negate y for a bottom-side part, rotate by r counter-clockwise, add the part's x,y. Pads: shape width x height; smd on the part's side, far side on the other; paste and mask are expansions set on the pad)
0201 [mm] "Data from Kemet datasheet CC101_COM dated 7/28/11"
  rect 0.46x0.42 smd mask+0.048: 1(-0.33,0) 2(0.33,0)
  body extent -0.31,-0.16 0.31,0.16, height 0.26
0201_033 [mm] "SMD, 2-Leads, Height 0.33mm"
  rect 0.46x0.42 smd mask+0.048: 1(-0.33,0) 2(0.33,0)
  body extent -0.31,-0.16 0.31,0.16, height 0.33
0201_033L [mm] "0201"
  rect 0.36x0.32 smd mask+0.048: 1(-0.28,0) 2(0.28,0)
  body extent -0.31,-0.16 0.31,0.16, height 0.33
0402 [mm] "0402 from SM-752 data"
  rect 0.8x0.6 smd: 1(-0.6,0) 2(0.6,0)
  silkscreen extent -1.22,-0.52 1.22,0.52, body extent -0.55,-0.3 0.55,0.3, height 0.6
0402_065 [mm] "0402"
  rect 0.8x0.6 smd: 1(-0.6,0) 2(0.6,0)
  silkscreen extent -1.22,-0.52 1.22,0.52, body extent -0.55,-0.3 0.55,0.3, height 0.65
0603 [mm] "0603 from SM-752 data"
  rect 1x0.95 smd: 1(-0.8,0) 2(0.8,0)
  silkscreen extent -1.52,-0.69 1.52,0.69, body extent -0.87,-0.47 0.87,0.47, height 1
0805_HV [mil] "0805 with 30mil clearance between pads"
  rect 50x63 smd: 1(-40,0) 2(40,0)
  silkscreen extent -74,-40 74,40, body extent -43,-29 43,29, height 57
AssemblyNote [mil] "Assembly Note"
AssemblyNoteLabel [mil] "Assembly Note for PCB Labels"
CE_Mark_5mm [mil] "Minimum text height for CE Mark"
  silkscreen extent -138,-98 138,98
D0650#1 [mm]
  rrect50% 0.27x0.794 smd paste-0.037 mask-0.274: 1(-2.8,0.665) 2(-2.8,-0.665) 3(-2.4,0.665) 4(-2.4,-0.665) 5(-2,0.665) 7(-1.6,0.665) 8(-1.6,-0.665) 10(-1.2,-0.665) 11(-0.8,0.665) 12(-0.8,-0.665) 13(-0.4,0.665) 14(-0.4,-0.665) 15(0,0.665) 16(0,-0.665) 17(0.4,0.665) 18(0.4,-0.665) 19(0.8,0.665) 20(0.8,-0.665) 21(1.2,0.665) 22(1.2,-0.665) 23(1.6,0.665) 24(1.6,-0.665) 25(2,0.665) 26(2,-0.665) 27(2.4,0.665) 28(2.4,-0.665) 29(2.8,0.665) 30(2.8,-0.665)
  rrect50% 0.27x0.794 smd paste-0.037 mask-0.24: 6(-2,-0.665)
  rrect50% 0.27x0.795 smd paste-0.037 mask-0.274: 9(-1.2,0.665)
  oval 0.18x0.7 on Top Solder paste-0.18 mask+0: ""(-2.8,0.665) ""(-2.8,-0.665) ""(-2.4,0.665) ""(-2.4,-0.665) ""(-2,0.665) ""(-2,-0.665) ""(-1.6,0.665) ""(-1.6,-0.665) ""(-1.2,0.665) ""(-1.2,-0.665) ""(-0.8,0.665) ""(-0.8,-0.665) ""(-0.4,0.665) ""(-0.4,-0.665) ""(0,0.665) ""(0,-0.665) ""(0.4,0.665) ""(0.4,-0.665) ""(0.8,0.665) ""(0.8,-0.665) ""(1.2,0.665) ""(1.2,-0.665) ""(1.6,0.665) ""(1.6,-0.665) ""(2,0.665) ""(2,-0.665) ""(2.4,0.665) ""(2.4,-0.665) ""(2.8,0.665) ""(2.8,-0.665)
  silkscreen extent -3.13,-1.25 3.13,1.31, body extent -3.02,-1.15 3.03,1.16, height 0.79
D0650#2 [mm]
  rrect50% 0.27x0.794 smd paste-0.037 mask-0.274: 1(-2.8,0.665) 2(-2.8,-0.665) 3(-2.4,0.665) 4(-2.4,-0.665) 5(-2,0.665) 7(-1.6,0.665) 8(-1.6,-0.665) 10(-1.2,-0.665) 11(-0.8,0.665) 12(-0.8,-0.665) 13(-0.4,0.665) 14(-0.4,-0.665) 15(0,0.665) 16(0,-0.665) 17(0.4,0.665) 18(0.4,-0.665) 19(0.8,0.665) 20(0.8,-0.665) 21(1.2,0.665) 22(1.2,-0.665) 23(1.6,0.665) 24(1.6,-0.665) 25(2,0.665) 26(2,-0.665) 27(2.4,0.665) 28(2.4,-0.665) 29(2.8,0.665) 30(2.8,-0.665)
  rrect50% 0.27x0.794 smd paste-0.037 mask-0.24: 6(-2,-0.665)
  rrect50% 0.27x0.795 smd paste-0.037 mask-0.274: 9(-1.2,0.665)
  oval 0.18x0.7 on Bottom Solder paste-0.18 mask+0: ""(-2.8,0.665) ""(-2.8,-0.665) ""(-2.4,0.665) ""(-2.4,-0.665) ""(-2,0.665) ""(-2,-0.665) ""(-1.6,0.665) ""(-1.6,-0.665) ""(-1.2,0.665) ""(-1.2,-0.665) ""(-0.8,0.665) ""(-0.8,-0.665) ""(-0.4,0.665) ""(-0.4,-0.665) ""(0,0.665) ""(0,-0.665) ""(0.4,0.665) ""(0.4,-0.665) ""(0.8,0.665) ""(0.8,-0.665) ""(1.2,0.665) ""(1.2,-0.665) ""(1.6,0.665) ""(1.6,-0.665) ""(2,0.665) ""(2,-0.665) ""(2.4,0.665) ""(2.4,-0.665) ""(2.8,0.665) ""(2.8,-0.665)
  silkscreen extent -3.13,-1.25 3.13,1.31, body extent -3.02,-1.15 3.03,1.16, height 0.79
DBV0005A-MFG [mm]
  rrect17% 1.1x0.6 smd paste+0 mask+0: 1(-1.3,0.95) 2(-1.3,0) 3(-1.3,-0.95) 4(1.3,-0.95) 5(1.3,0.95)
  silkscreen extent -2.52,-1.53 0.87,1.53, body extent -1.4,-1.45 1.4,1.45, height 1.45
DEC0002A [mm] "X1SON-2"
  rrect57% 0.35x0.6 smd paste-0.5 mask-0.05: 1(-0.325,0) 2(0.325,0)
  rrect33% 0.3x0.5 on Top Paste: 1S(-0.35,0) 2S(0.35,0)
  body extent -0.5,-0.3 0.5,0.3, height 0.5
DRS0006A#1 [mm] "SON, 6-Leads, Body 3x3mm, Pitch 0.95mm, Thermal Pad 2x1.3mm, TI Recommended"
  rrect100% 0.7x0.35 smd: 1(-1.35,0.95) 2(-1.35,0) 3(-1.35,-0.95) 4(1.35,-0.95) 5(1.35,0) 6(1.35,0.95)
  rrect9% 1.126x1.71 on Bottom Paste: 7(0,0)
  rrect8% 1.2x1.9 smd paste-0.6: 7(0,0)
  silkscreen extent -1.73,-1.73 1.72,1.73, body extent -1.58,-1.57 1.57,1.58, height 0.81
DRS0006A#2 [mm] "SON, 6-Leads, Body 3x3mm, Pitch 0.95mm, Thermal Pad 2x1.3mm, TI Recommended"
  rrect100% 0.7x0.35 smd: 1(-1.35,0.95) 2(-1.35,0) 3(-1.35,-0.95) 4(1.35,-0.95) 5(1.35,0) 6(1.35,0.95)
  rrect9% 1.126x1.71 on Top Paste: 7(0,0)
  rrect8% 1.2x1.9 smd paste-0.6: 7(0,0)
  silkscreen extent -1.73,-1.73 1.72,1.73, body extent -1.58,-1.57 1.57,1.58, height 0.81
DRV0006A [mm] "SON, 6-Leads, Body 2x2mm, Pitch 0.65mm, Thermal Pad 1.6x1mm, TI Recommended"
  rrect33% 0.45x0.3 smd: 1(-0.975,0.65) 2(-0.975,0) 3(-0.975,-0.65) 4(0.975,-0.65) 5(0.975,0) 6(0.975,0.65)
  rrect14% 1x0.7 on Top Paste: 7(0,-0.45) 7(0,0.45)
  rrect10% 1x1.6 smd paste-0.5: 7(0,0)
  silkscreen extent -1.05,-1.2 1.05,1.2, body extent -1.05,-1.05 1.05,1.05, height 0.81
FCC_disclaimer [mil]
FP-C1206C224K3JAC7800_1206-MFG [mm]
  rrect11% 0.95x1.7 smd paste+0 mask+0: 1(-1.4,0) 2(1.4,0)
  silkscreen extent -0.55,-0.9 0.55,0.9, body extent -1.6,-0.8 1.6,0.8, height 1.8
FP-C2012X5R2A475K125AC_0805-MFG [mm]
  rrect13% 0.8x1.05 smd paste+0 mask+0: 1(-0.925,0) 2(0.925,0)
  silkscreen extent -0.15,-0.75 0.15,0.75, body extent -1.43,-0.85 1.43,0.85, height 0.25
FP-CC0603KRX5R6BB106_0603-MFG [mm] "0603 from SM-752 data"
  rrect13% 0.8x0.9 smd paste+0 mask+0: 1(-0.75,0) 2(0.75,0)
  silkscreen extent -0.85,-0.87 0.85,0.87, body extent -0.8,-0.4 0.8,0.4, height 1
FP-FTSH-104-04-L-D-RA_HDR8-MFG [mm]
  rrect9% 1.12x1.12 hole 0.71 paste-2539.97 mask+0: 1(-1.905,2.525)
  round 1.12 hole 0.71 paste-2539.97 mask+0: 2(-1.905,3.795) 3(-0.635,2.525) 4(-0.635,3.795) 5(0.635,2.525) 6(0.635,3.795) 7(1.905,2.525) 8(1.905,3.795)
  silkscreen extent -3.29,-1.32 2.57,2.65, body extent -2.5,-5.07 2.5,4, height 3.56
FP-GRM155C81C225ME15D_0402-MFG [mm]
  rrect22% 0.45x0.6 smd paste+0 mask+0: 1(-0.475,0) 2(0.475,0)
  silkscreen extent -0.61,-0.67 0.6,0.67, body extent -0.5,-0.25 0.5,0.25, height 0.55
"FP-RC0201JR-070RL_0201 (0603 Metric)-IPC_C" [mil]
  rrect38% 13.94x10.34 smd paste+0 mask+0: 1(-10.01,0) 2(10.01,0)
  body extent -12,-6 12,6, height 10
Mill-Max_3621-0-32-xx-00-00-08-0 [mm] "PCB Pin, 0.04\" DIA, R/A, Edge-Mount"
  rrect50% 3.18x3.18 hole 1.65: 1(0,2.388)
  body extent -1.59,-5.06 1.59,3.98, height 1.57
NetTie_0402 [mm] "Net Tie 0402 size"
  rect 0.6x0.5 smd paste-0.5: 1(-0.5,0) 2(0.5,0)
  Top Layer region: -0.279,0.203 0.279,0.203 0.279,-0.203 -0.279,-0.203
RAR0016A-MFG [mm]
  round 0.265 smd paste+0 mask-1000: 1(-1.925,2.375) 11(1.925,2.375)
  rrect40% 0.7x0.25 smd paste+0 mask-1000: 2(-2.1,1.825) 3(-2.1,1.325) 4(-2.1,0.825) 8(2.1,0.825) 9(2.1,1.325) 10(2.1,1.825)
  rrect25% 0.8x2.6 smd paste-1000 mask-1000: 5(-2.1,-1.35) 7(2.1,-1.35)
  round 1.813 smd paste-1000 mask-1000: 6(-0.034,0.943)
  rrect40% 0.25x0.7 smd paste+0 mask-1000: 12(0.825,2.6) 13(0.325,2.6) 14(-0.175,2.6) 15(-0.675,2.6) 16(-1.175,2.6)
  Top Layer region: -1.45,1.85 -1.437,1.9 -1.4,1.937 -1.35,1.95 -1.35,1.95 0.9,1.95 0.938,1.942 0.971,1.921 0.992,1.888 1,1.85 1,1.85 1,-2.9 0.987,-2.95 0.95,-2.987 0.9,-3 0.9,-3 -0.9,-3 -0.95,-2.987 -0.987,-2.95 -1,-2.9 -1,-2.9 -1,0.585 -1.004,0.604 -1.015,0.62 -1.031,0.631 -1.05,0.635 -1.05,0.635 -1.35,0.635 -1.388,0.643 -1.421,0.664 -1.442,0.697 -1.45,0.735 -1.45,0.735
  Top Layer region: 2.4,2.2 2.419,2.204 2.435,2.215 2.446,2.231 2.45,2.25 2.45,2.25 2.45,2.4 2.443,2.425 2.425,2.443 2.4,2.45 2.4,2.45 2.1,2.45 2.062,2.458 2.029,2.479 2.008,2.512 2,2.55 2,2.55 2,2.9 1.993,2.925 1.975,2.943 1.95,2.95 1.95,2.95 1.8,2.95 1.775,2.943 1.757,2.925 1.75,2.9 1.75,2.9 1.75,2.25 1.754,2.231 1.765,2.215 1.781,2.204 1.8,2.2 1.8,2.2
  Top Layer region: -2.4,2.2 -2.419,2.204 -2.435,2.215 -2.446,2.231 -2.45,2.25 -2.45,2.25 -2.45,2.4 -2.443,2.425 -2.425,2.443 -2.4,2.45 -2.4,2.45 -2.1,2.45 -2.062,2.458 -2.029,2.479 -2.008,2.512 -2,2.55 -2,2.55 -2,2.9 -1.993,2.925 -1.975,2.943 -1.95,2.95 -1.95,2.95 -1.8,2.95 -1.781,2.946 -1.765,2.935 -1.754,2.919 -1.75,2.9 -1.75,2.9 -1.75,2.25 -1.754,2.231 -1.765,2.215 -1.781,2.204 -1.8,2.2 -1.8,2.2
  silkscreen extent -3.18,-3.1 2.65,3.1, body extent -2.6,-3.1 2.6,3.05, height 0.25
RHB0032E-MFG [mm]
  rrect40% 0.6x0.25 smd paste+0 mask+0: 1(-2.4,1.75) 2(-2.4,1.25) 3(-2.4,0.75) 4(-2.4,0.25) 5(-2.4,-0.25) 6(-2.4,-0.75) 7(-2.4,-1.25) 8(-2.4,-1.75) 17(2.4,-1.75) 18(2.4,-1.25) 19(2.4,-0.75) 20(2.4,-0.25) 21(2.4,0.25) 22(2.4,0.75) 23(2.4,1.25) 24(2.4,1.75)
  rrect40% 0.25x0.6 smd paste+0 mask+0: 9(-1.75,-2.4) 10(-1.25,-2.4) 11(-0.75,-2.4) 12(-0.25,-2.4) 13(0.25,-2.4) 14(0.75,-2.4) 15(1.25,-2.4) 16(1.75,-2.4) 25(1.75,2.4) 26(1.25,2.4) 27(0.75,2.4) 28(0.25,2.4) 29(-0.25,2.4) 30(-0.75,2.4) 31(-1.25,2.4) 32(-1.75,2.4)
  rrect3% 3.45x3.45 smd paste-1000 mask+0: 33(0,0)
  silkscreen extent -3.37,-2.55 2.55,2.55, body extent -2.8,-2.8 2.8,2.8, height 0.25
TI_Symbol_Overlay_Small [mil]
  silkscreen extent -90,-88 91,88
TP_25MIL-SMT [mil]
  round 25 smd mask-2.5: 1(0,0)
WEEE_Minimum [mil] "WEEElie bin"
  silkscreen extent -95,-172 99,104

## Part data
C1 C2 C3 C4 C5 C6 C7 C8 C9 C10 C137 C138: library part CMP-0098058-1, "4.7 µF ±10% 100V Ceramic Capacitor X5R 0805 (2012 Metric)", Digikey Part Number=445-C2012X5R2A475K125ACCT-ND, Manufacturer=TDK, Mouser Part Number=810-C2012X5R2A475K12, Operating Temperature Range="-55°C to +85°C", TempCo=15%, Temperature Characteristic=X5R, Tolerance_%=10%, ValueDisplayed=4.7uF
C11 C38 C42 C80 C83 C84: library part CMP-0064909-1, "CAP, CERM, 1 uF, 10 V,+/- 20%, X5R, 0201", Cap_Case=0201, Manufacturer=MuRata, Supplier Part Number 1=490-13226-1-ND, TempCo=X5R, Tolerance_%=20%, Value1=Unknown, Value2=10V, ValueDisplayed=1uF
C12 C13 C48 C50: library part CMP-0006204-2, "CAP, CERM, 0.1 uF, 16 V, +/- 10%, X5R, 0402", Cap_Case=0402, Manufacturer="Johanson Technology", Supplier Part Number 1=709-1129-1-ND, TempCo=X5R, Tolerance_%=10%, Value1=Unknown, Value2=16V, ValueDisplayed=0.1uF
C14 C15 C16 C17 C18 C19 C20 C21 C22 C23 C24 C25 C26 C27 C28 C29 C30 C31 C32 C33 C34 C35 C36 C37 C51 C52 C53 C54 C55 C56 C57 C58 C59 C60 C61 C62 C66 C67 C68 C69 C70 C71 C72 C73 C74 C75 C76 C77: library part CMP-0001414-1, "Chip Multilayer Ceramic Capacitors for General Purpose, 0402, 2.2uF, X6S, 22%, 20%, 16V", Manufacturer=Murata, Operating Temperature Range="-55°C to +105°C", TempCo=22%, Temperature Characteristic=X6S, Tolerance_%=20%, ValueDisplayed=2.2uF
C39 C40 C41 C43 C44 C45 C46 C47 C49 C63 C64 C65 C78 C79 C81 C82: library part CMP-0001410-1, "0.22 µF ±10% 25V Ceramic Capacitor U2J 1206 (3216 Metric)", Digikey Part Number=399-16917-1-ND, Manufacturer=KEMET, Mouser Part Number=80-C1206C224K3J, Operating Temperature Range="-55°C to +125°C", TempCo=-750+/-120ppm/°C, Temperature Characteristic=U2J, Tolerance_%=10%, ValueDisplayed=0.22uF
C85: library part CMP-0086060-1, "CAP, CERM, 0.01 µF, 25 V,+/- 10%, X5R, 0201", Cap_Case=0201, Manufacturer=MuRata, TempCo=X5R, Tolerance_%=10%, Value2=25V, ValueDisplayed=0.01µF
C86 C87 C92 C93 C94 C95 C97 C98 C99 C110 C111 C112 C113 C114 C129 C130 C131 C132: library part CMP-0086057-1, "CAP, CERM, 10 pF, 50 V,+/- 5%, C0G/NP0, 0201", Cap_Case=0201, Manufacturer=MuRata, TempCo=C0G/NP0, Tolerance_%=5%, Value2=50V, ValueDisplayed=10pF
C88 C89: library part CMP-0009752-1, "CAP, CERM, 2200 pF, 16 V, +/- 10%, X7R, 0201", Cap_Case=0201, Manufacturer=MuRata, Supplier Part Number 1=490-3190-1-ND, TempCo=X7R, Tolerance_%=10%, Value1=Unknown, Value2=16V, ValueDisplayed=2200pF
C90 C91: library part CMP-0009661-3, "CAP, CERM, 10 pF, 25 V, +/- 5%, C0G/NP0, 0201", Cap_Case=0201, Manufacturer=MuRata, Supplier Part Number 1=GJM0335C1E100JB01D-ND, TempCo=C0G/NP0, Tolerance_%=5%, Value1=Unknown, Value2=25V, ValueDisplayed=10pF
C96: library part CMP-0092309-1, "Cap Ceramic 10uF 10V X5R 10% SMD 0603 85C Paper T/R", Digikey Part Number=311-1782-1-ND, Manufacturer=YAGEO, Mouser Part Number=603-CC603KRX5R6BB106, Octopart Part Number=1f0ad7d7c223c0cd, Operating Temperature Range="-55°C to +85°C", TempCo=15%, Temperature Characteristic=X5R, Tolerance_%=10%, ValueDisplayed=10uF
C100 C133 C135 C136: library part CMP-0064970-1, "CAP, CERM, 0.1 uF, 16 V,+/- 10%, X7R, 0201", Cap_Case=0201, Manufacturer=MuRata, Supplier Part Number 1=81-GRM033Z71C104KE4D, TempCo=X7R, Tolerance_%=10%, Value1=Unknown, Value2=16V, ValueDisplayed=0.1uF
C101: library part CMP-0007323-5, "CAP, CERM, 2.2 uF, 10 V, +/- 10%, X5R, 0603", Cap_Case=0603, Manufacturer=MuRata, Supplier Part Number 1=490-1545-1-ND, TempCo=X5R, Tolerance_%=10%, Value1=Unknown, Value2=10V, ValueDisplayed=2.2uF
C103 C104 C108 C109: library part CMP-0009745-1, "CAP, CERM, 1000 pF, 16 V, +/- 10%, X7R, 0201", Cap_Case=0201, Manufacturer=MuRata, Supplier Part Number 1=GRM033R71C102KA01D-ND, TempCo=X7R, Tolerance_%=10%, Value1=Unknown, Value2=16V, ValueDisplayed=1000pF
C105 C107: library part CMP-0009652-3, "CAP, CERM, 220 pF, 50 V, +/- 10%, X7R, AEC-Q200 Grade 1, 0201", Cap_Case=0201_033, Manufacturer=TDK, Supplier Part Number 1=445-12109-1-ND, TempCo=X7R, Tolerance_%=10%, Value1="11.6275 ohm", Value2=50V, ValueDisplayed=220pF
C106: library part CMP-0076713-1, "CAP, CERM, 0.1 µF, 10 V,+/- 10%, X5R, 0201", Cap_Case=0201, Manufacturer="AT Ceramics", TempCo=X5R, Tolerance_%=10%, Value2=10V, ValueDisplayed=0.1µF
C115 C116 C117 C118 C119 C120 C121 C122: library part CMP-0084680-1, "CAP, CERM, 22 µF, 25 V,+/- 20%, X5R, AEC-Q200 Grade 3, 0805", Cap_Case=0805, Manufacturer=MuRata, TempCo=X5R, Tolerance_%=20%, Value2=25V, ValueDisplayed=22µF
C123 C124 C125 C126 C127 C128: library part CMP-0006618-2, "CAP, CERM, 0.1 uF, 100 V, +/- 10%, X5R, 0402", Cap_Case=0402, Manufacturer=MuRata, Supplier Part Number 1=490-10458-1-ND, TempCo=X5R, Tolerance_%=10%, Value1=Unknown, Value2=100V, ValueDisplayed=0.1uF
C134: library part CMP-0007158-5, "CAP, CERM, 22 uF, 10 V, +/- 20%, X5R, 0603", Cap_Case=0603, Manufacturer=MuRata, Supplier Part Number 1=490-13243-1-ND, TempCo=X5R, Tolerance_%=20%, Value1=Unknown, Value2=10V, ValueDisplayed=22uF
Gnd1 Gnd2 Gnd3 Gnd4 Gnd5 Gnd6 Vin1 Vout1 Vout2 Vout3 Vout4 Vout5 Vout6: library part CMP-0082316-1, "PCB Pin, 0.04\" DIA, Edge-Mount", Manufacturer=Mill-Max, Supplier Part Number 1=575-3621032150000
J1: library part CMP-0003661-1, "Like part: FTSH-104-04-L-D-RA", Current_A=3.4A, Digikey Part Number=FTSH-104-04-L-D-RA-ND, Manufacturer=Samtec, Mouser Part Number=200-FTSH10404LDRA, Operating Temperature Range="-55°C to +125°C", Part Number=FTSH-104-04-L-D-RA
L1 L2 L3 L4: library part CMP-0084501-1, "Inductor, Ferrite Bead, Ferrite, 0.35 A, 0.38 ohm, SMD", Manufacturer=MuRata, Value1="0.38 ohm", Value2=0.35A
Logo1: library part CMP-0074844-1
Logo2: library part CMP-0074838-1, "Texas Instrument Corporate Signature"
Logo3: library part CMP-0074847-1, "FCC_disclaimer"
Logo4: library part CMP-0074769-1
NT1: library part CMP-0078142-6, "Single point connection between nets.", Manufacturer=N/A
Q1 Q2 Q3 Q4 Q5 Q6 Q7 Q8: "40V 1.1mE 90A", Supplier Part Number 1=917-EPC2066TR-ND
R1 R11 R19 R22 R30 R38 R39 R44 R45: library part CMP-0086442-2, "RES SMD 0 OHM JUMPER 1/20W 0201", Manufacturer=Yageo, Power_W=50mW, TempCo=200ppm/°C, Tolerance_%=5%
R2 R6 R33 R35: library part CMP-0027021-3, "RES, 10, 5%, 0.05 W, 0201", Manufacturer="Yageo America", Power_W=50mW, Supplier Part Number 1=311-10NCT-ND, TempCo="350 ppm/C", Tolerance_%=5%, Value2=0.05W, Value_Code=10R0, ValueDisplayed=10
R3 R5 R7 R37 R40 R41 R42 R43: library part CMP-0028098-1, "RES, 2.00, 1%, 0.05 W, 0201", Manufacturer="Yageo America", Power_W=50mW, Supplier Part Number 1=603-RC0201FS-7D2RL, TempCo="350 ppm/C", Tolerance_%=1%, Value2=0.05W, Value_Code=2R00, ValueDisplayed=2.00
R4 R8 R34 R36: library part CMP-0028226-1, "RES, 5.11 k, 0.5%, 0.05 W, 0201", Manufacturer="Yageo America", Power_W=50mW, Supplier Part Number 1=RC0201DR-075K11L-ND, TempCo="200 ppm/C", Tolerance_%=0.5%, Value2=0.05W, Value_Code=5k11, ValueDisplayed=5.11k
R9: library part CMP-0027472-1, "RES, 1.00, 1%, 0.05 W, 0201", Manufacturer="Yageo America", Power_W=50mW, Supplier Part Number 1=YAG3368CT-ND, TempCo="350 ppm/C", Tolerance_%=1%, Value2=0.05W, Value_Code=1R00, ValueDisplayed=1.00
R10 R12: library part CMP-0027272-3, "RES, 2.20 k, 1%, 0.05 W, 0201", Manufacturer=Vishay-Dale, Power_W=50mW, Supplier Part Number 1=541-2.20KAABCT-ND, TempCo="100 ppm/C", Tolerance_%=1%, Value2=0.05W, Value_Code=2k20, ValueDisplayed=2.20k
R13: library part CMP-0026815-1, "RES, 100 k, 0.1%, 0.063 W, 0402", Manufacturer="Susumu Co Ltd", Power_W=63mW, Supplier Part Number 1=RG10P100KBCT-ND, TempCo="25 ppm/C", Tolerance_%=0.1%, Value2=0.063W, Value_Code=100k
R14 R15 R28 R29: library part CMP-0078192-2, "RES, 20.0, 1%, 0.05 W, 0201", Manufacturer=Vishay-Dale, Power_W=50mW, Supplier Part Number 1=541-2947-1-ND, TempCo="200 ppm/C", Tolerance_%=1%, Value2=0.05W, Value_Code=20R0, ValueDisplayed=20.0
R16 R26: library part CMP-0028084-1, "RES, 1.00 k, 1%, 0.05 W, 0201", Manufacturer="Yageo America", Power_W=50mW, Supplier Part Number 1=603-RC0201FS-7D1KL, TempCo="200 ppm/C", Tolerance_%=1%, Value2=0.05W, Value_Code=1k00, ValueDisplayed=1.00k
R17 R25: library part CMP-0860046-1, "RES, 14.0 k, 1%, 0.0625 W, 0402", Manufacturer=Yageo, Power_W=62.5mW, Supplier Part Number 1=311-14.0KLRCT-ND, TempCo="100 ppm/C", Tolerance_%=1%, Value2=0.0625W, Value_Code=14k0, ValueDisplayed=14.0k
R18: library part CMP-0028092-1, "RES, 24.3, 1%, 0.05 W, 0201", Manufacturer="Yageo America", Power_W=50mW, Supplier Part Number 1=603-RC0201FS-7D24R3L, TempCo="200 ppm/C", Tolerance_%=1%, Value2=0.05W, Value_Code=24R3, ValueDisplayed=24.3
R20: library part CMP-0027186-1, "RES, 10 k, 5%, 0.05 W, 0201", Manufacturer="Yageo America", Power_W=50mW, Supplier Part Number 1=603-RC0201JR-7D10KL, TempCo="200 ppm/C", Tolerance_%=5%, Value2=0.05W, Value_Code=10k0, ValueDisplayed=10k
R21: library part CMP-0026669-1, "RES, 150 k, 1%, 0.1 W, AEC-Q200 Grade 0, 0402", Manufacturer=Panasonic, Power_W=100mW, Supplier Part Number 1=P150KLCT-ND, TempCo="100 ppm/C", Tolerance_%=1%, Value2=0.1W, Value_Code=150k
R23: library part CMP-0027570-1, "RES, 2.80 k, 1%, 0.05 W, 0201", Manufacturer="Yageo America", Power_W=50mW, Supplier Part Number 1=YAG2583CT-ND, TempCo="200 ppm/C", Tolerance_%=1%, Value2=0.05W, Value_Code=2k80, ValueDisplayed=2.80k
R24: library part CMP-0027911-1, "RES, 8.66 k, 1%, 0.05 W, 0201", Manufacturer="Yageo America", Power_W=50mW, Supplier Part Number 1=YAG2834CT-ND, TempCo="200 ppm/C", Tolerance_%=1%, Value2=0.05W, Value_Code=8k66, ValueDisplayed=8.66k
R27: library part CMP-0027788-1, "RES, 5.11 k, 1%, 0.05 W, 0201", Manufacturer="Yageo America", Power_W=50mW, Supplier Part Number 1=YAG2740CT-ND, TempCo="200 ppm/C", Tolerance_%=1%, Value2=0.05W, Value_Code=5k11, ValueDisplayed=5.11k
R31 R32: library part CMP-0027260-1, "RES, 10 k, 5%, 0.05 W, 0201", Manufacturer="Yageo America", Power_W=50mW, Supplier Part Number 1=603-RC0201JS-7D10KL, TempCo="200 ppm/C", Tolerance_%=5%, Value2=0.05W, Value_Code=10k0, ValueDisplayed=10k
RT1 RT2: library part CMP-0084565-1, "Thermistor, DEC0002A (X1SON-2)", Alternate Manufacturer="Texas Instruments", Alternate PartNumber=TMP6131DECR
TP1 TP2 TP3 TP4 TP5 TP6 TP7 TP8 TP9 TP12 TP13 TP14 TP15: library part CMP-0078143-3, "TEST POINT.  No entry in BOM.", Manufacturer=N/A
U1 U3 U4 U6: library part CMP-0013422-3, "UCD7xxx Low Side Power MOSFET Driver with Body Diode Conduction Sensing, DRS0006A (WSON-6)", Alternate Manufacturer="Texas Instruments"
U2 U5: library part CMP-0097820-2, Manufacturer="Texas Instruments", Operating Temperature Range=to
